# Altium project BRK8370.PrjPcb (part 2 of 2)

## Sheet QSFP-GTH.SchDoc: QSFP-GTH
size C; Author: Casey Smith; Organization: Opal Kelly; Address1: 13500 SW 72nd Ave STE 100; Address2: Portland, OR 97223; Address3: 217.391.3724; Address4: http://www.opalkelly.com; DocumentNumber: 5; Revision: 1; SheetNumber: 5; SheetTotal: 8
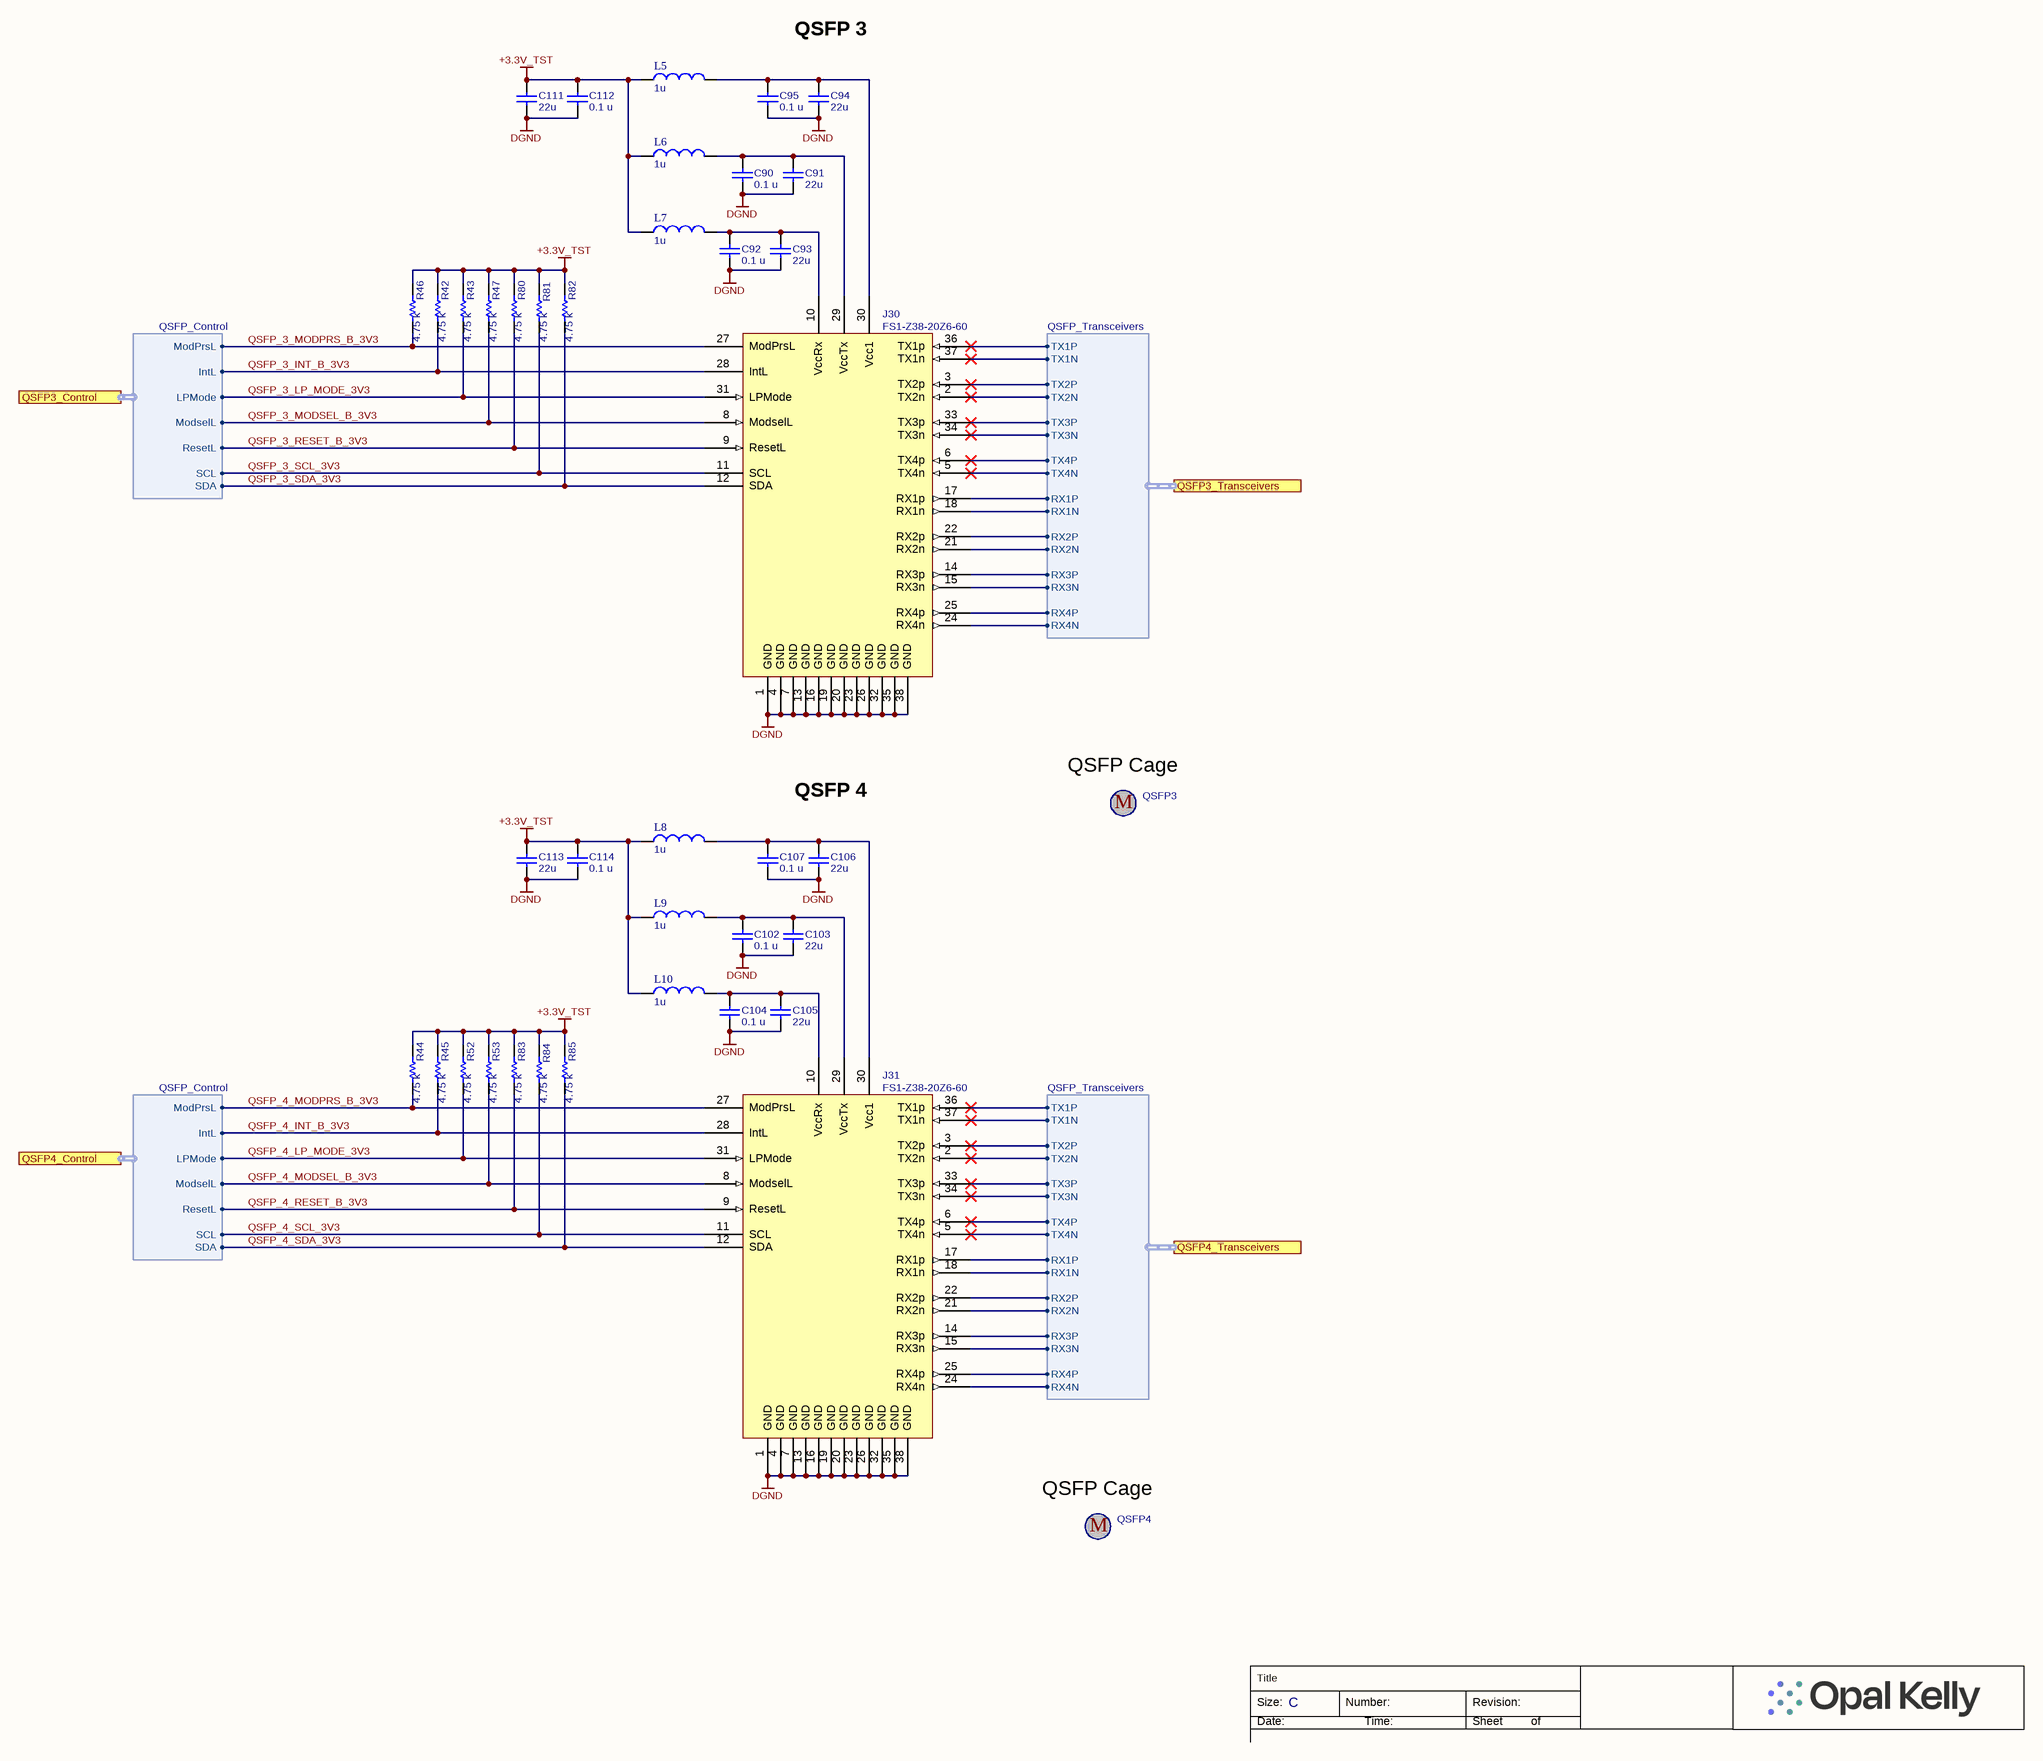
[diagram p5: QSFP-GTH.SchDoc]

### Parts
C90  value 0.1 u  [CAPC1005X06A]  (hidden comment: SM-0402, 10%, 10v)
C91  value 22u  [CAPC3216N]  (hidden comment: SM-1206, 10%, 10v, X7R)
C92  value 0.1 u  [CAPC1005X06A]  (hidden comment: SM-0402, 10%, 10v)
C93  value 22u  [CAPC3216N]  (hidden comment: SM-1206, 10%, 10v, X7R)
C94  value 22u  [CAPC3216N]  (hidden comment: SM-1206, 10%, 10v, X7R)
C95  value 0.1 u  [CAPC1005X06A]  (hidden comment: SM-0402, 10%, 10v)
C102  value 0.1 u  [CAPC1005X06A]  (hidden comment: SM-0402, 10%, 10v)
C103  value 22u  [CAPC3216N]  (hidden comment: SM-1206, 10%, 10v, X7R)
C104  value 0.1 u  [CAPC1005X06A]  (hidden comment: SM-0402, 10%, 10v)
C105  value 22u  [CAPC3216N]  (hidden comment: SM-1206, 10%, 10v, X7R)
C106  value 22u  [CAPC3216N]  (hidden comment: SM-1206, 10%, 10v, X7R)
C107  value 0.1 u  [CAPC1005X06A]  (hidden comment: SM-0402, 10%, 10v)
C111  value 22u  [CAPC3216N]  (hidden comment: SM-1206, 10%, 10v, X7R)
C112  value 0.1 u  [CAPC1005X06A]  (hidden comment: SM-0402, 10%, 10v)
C113  value 22u  [CAPC3216N]  (hidden comment: SM-1206, 10%, 10v, X7R)
C114  value 0.1 u  [CAPC1005X06A]  (hidden comment: SM-0402, 10%, 10v)
J30  FS1-Z38-20Z6-60  [QSFP28_RECEPTACLE_SFF-8679]
J31  FS1-Z38-20Z6-60  [QSFP28_RECEPTACLE_SFF-8679]
L5  value 1u  [CIGT252010]  (hidden comment: CIGT252010LM1R0MNE)
L6  value 1u  [CIGT252010]  (hidden comment: CIGT252010LM1R0MNE)
L7  value 1u  [CIGT252010]  (hidden comment: CIGT252010LM1R0MNE)
L8  value 1u  [CIGT252010]  (hidden comment: CIGT252010LM1R0MNE)
L9  value 1u  [CIGT252010]  (hidden comment: CIGT252010LM1R0MNE)
L10  value 1u  [CIGT252010]  (hidden comment: CIGT252010LM1R0MNE)
QSFP3  Pressfit  [QSFP28_SINGLE_CAGE]  (value not drawn)
QSFP4  Pressfit  [QSFP28_SINGLE_CAGE]  (value not drawn)
R42  value 4.75 k  [RESC1005X06A]  (hidden comment: CRCW04024K75FKED)
R43  value 4.75 k  [RESC1005X06A]  (hidden comment: CRCW04024K75FKED)
R44  value 4.75 k  [RESC1005X06A]  (hidden comment: CRCW04024K75FKED)
R45  value 4.75 k  [RESC1005X06A]  (hidden comment: CRCW04024K75FKED)
R46  value 4.75 k  [RESC1005X06A]  (hidden comment: CRCW04024K75FKED)
R47  value 4.75 k  [RESC1005X06A]  (hidden comment: CRCW04024K75FKED)
R52  value 4.75 k  [RESC1005X06A]  (hidden comment: CRCW04024K75FKED)
R53  value 4.75 k  [RESC1005X06A]  (hidden comment: CRCW04024K75FKED)
R80  value 4.75 k  [RESC1005X06A]  (hidden comment: CRCW04024K75FKED)
R81  value 4.75 k  [RESC1005X06A]  (hidden comment: CRCW04024K75FKED)
R82  value 4.75 k  [RESC1005X06A]  (hidden comment: CRCW04024K75FKED)
R83  value 4.75 k  [RESC1005X06A]  (hidden comment: CRCW04024K75FKED)
R84  value 4.75 k  [RESC1005X06A]  (hidden comment: CRCW04024K75FKED)
R85  value 4.75 k  [RESC1005X06A]  (hidden comment: CRCW04024K75FKED)

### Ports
QSFP3_Control (harness QSFP_Control), QSFP3_Transceivers (harness QSFP_Transceivers), QSFP4_Control (harness QSFP_Control), QSFP4_Transceivers (harness QSFP_Transceivers)

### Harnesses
QSFP_Transceivers: TX1P, TX1N, TX2P, TX2N, TX3P, TX3N, TX4P, TX4N, RX1P, RX1N, RX2P, RX2N, RX3P, RX3N, RX4P, RX4N
QSFP_Control: ModPrsL, IntL, LPMode, ModselL, ResetL, SCL, SDA

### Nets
+3.3V_TST: C111.2 C112.2 C113.2 C114.2 L5.1 L6.1 L7.1 L8.1 L9.1 L10.1 R42.2 R43.2 R44.2 R45.2 R46.2 R47.2 R52.2 R53.2 R80.2 R81.2 R82.2 R83.2 R84.2 R85.2
DGND: C90.1 C91.1 C92.1 C93.1 C94.1 C95.1 C102.1 C103.1 C104.1 C105.1 C106.1 C107.1 C111.1 C112.1 C113.1 C114.1 J30.1(GND) J30.4(GND) J30.7(GND) J30.13(GND) J30.16(GND) J30.19(GND) J30.20(GND) J30.23(GND) J30.26(GND) J30.32(GND) J30.35(GND) J30.38(GND) J31.1(GND) J31.4(GND) J31.7(GND) J31.13(GND) J31.16(GND) J31.19(GND) J31.20(GND) J31.23(GND) J31.26(GND) J31.32(GND) J31.35(GND) J31.38(GND)
QSFP_3_INT_B_3V3: J30.28(IntL) R42.1 ; port QSFP3_Control.IntL
QSFP_3_LP_MODE_3V3: J30.31(LPMode) R43.1 ; port QSFP3_Control.LPMode
QSFP_3_MODPRS_B_3V3: J30.27(ModPrsL) R46.1 ; port QSFP3_Control.ModPrsL
QSFP_3_MODSEL_B_3V3: J30.8(ModselL) R47.1 ; port QSFP3_Control.ModselL
QSFP_3_RESET_B_3V3: J30.9(ResetL) R80.1 ; port QSFP3_Control.ResetL
QSFP_3_RX1_N: J30.18(RX1n) ; port QSFP3_Transceivers.RX1N
QSFP_3_RX1_P: J30.17(RX1p) ; port QSFP3_Transceivers.RX1P
QSFP_3_RX2_N: J30.21(RX2n) ; port QSFP3_Transceivers.RX2N
QSFP_3_RX2_P: J30.22(RX2p) ; port QSFP3_Transceivers.RX2P
QSFP_3_RX3_N: J30.15(RX3n) ; port QSFP3_Transceivers.RX3N
QSFP_3_RX3_P: J30.14(RX3p) ; port QSFP3_Transceivers.RX3P
QSFP_3_RX4_N: J30.24(RX4n) ; port QSFP3_Transceivers.RX4N
QSFP_3_RX4_P: J30.25(RX4p) ; port QSFP3_Transceivers.RX4P
QSFP_3_SCL_3V3: J30.11(SCL) R81.1 ; port QSFP3_Control.SCL
QSFP_3_SDA_3V3: J30.12(SDA) R82.1 ; port QSFP3_Control.SDA
QSFP_3_TX1_N: J30.37(TX1n) ; port QSFP3_Transceivers.TX1N
QSFP_3_TX1_P: J30.36(TX1p) ; port QSFP3_Transceivers.TX1P
QSFP_3_TX2_N: J30.2(TX2n) ; port QSFP3_Transceivers.TX2N
QSFP_3_TX2_P: J30.3(TX2p) ; port QSFP3_Transceivers.TX2P
QSFP_3_TX3_N: J30.34(TX3n) ; port QSFP3_Transceivers.TX3N
QSFP_3_TX3_P: J30.33(TX3p) ; port QSFP3_Transceivers.TX3P
QSFP_3_TX4_N: J30.5(TX4n) ; port QSFP3_Transceivers.TX4N
QSFP_3_TX4_P: J30.6(TX4p) ; port QSFP3_Transceivers.TX4P
QSFP_4_INT_B_3V3: J31.28(IntL) R45.1 ; port QSFP4_Control.IntL
QSFP_4_LP_MODE_3V3: J31.31(LPMode) R52.1 ; port QSFP4_Control.LPMode
QSFP_4_MODPRS_B_3V3: J31.27(ModPrsL) R44.1 ; port QSFP4_Control.ModPrsL
QSFP_4_MODSEL_B_3V3: J31.8(ModselL) R53.1 ; port QSFP4_Control.ModselL
QSFP_4_RESET_B_3V3: J31.9(ResetL) R83.1 ; port QSFP4_Control.ResetL
QSFP_4_RX1_N: J31.18(RX1n) ; port QSFP4_Transceivers.RX1N
QSFP_4_RX1_P: J31.17(RX1p) ; port QSFP4_Transceivers.RX1P
QSFP_4_RX2_N: J31.21(RX2n) ; port QSFP4_Transceivers.RX2N
QSFP_4_RX2_P: J31.22(RX2p) ; port QSFP4_Transceivers.RX2P
QSFP_4_RX3_N: J31.15(RX3n) ; port QSFP4_Transceivers.RX3N
QSFP_4_RX3_P: J31.14(RX3p) ; port QSFP4_Transceivers.RX3P
QSFP_4_RX4_N: J31.24(RX4n) ; port QSFP4_Transceivers.RX4N
QSFP_4_RX4_P: J31.25(RX4p) ; port QSFP4_Transceivers.RX4P
QSFP_4_SCL_3V3: J31.11(SCL) R84.1 ; port QSFP4_Control.SCL
QSFP_4_SDA_3V3: J31.12(SDA) R85.1 ; port QSFP4_Control.SDA
QSFP_4_TX1_N: J31.37(TX1n) ; port QSFP4_Transceivers.TX1N
QSFP_4_TX1_P: J31.36(TX1p) ; port QSFP4_Transceivers.TX1P
QSFP_4_TX2_N: J31.2(TX2n) ; port QSFP4_Transceivers.TX2N
QSFP_4_TX2_P: J31.3(TX2p) ; port QSFP4_Transceivers.TX2P
QSFP_4_TX3_N: J31.34(TX3n) ; port QSFP4_Transceivers.TX3N
QSFP_4_TX3_P: J31.33(TX3p) ; port QSFP4_Transceivers.TX3P
QSFP_4_TX4_N: J31.5(TX4n) ; port QSFP4_Transceivers.TX4N
QSFP_4_TX4_P: J31.6(TX4p) ; port QSFP4_Transceivers.TX4P
NetC90_2: C90.2 C91.2 J30.29(VccTx) L6.2
NetC92_2: C92.2 C93.2 J30.10(VccRx) L7.2
NetC94_2: C94.2 C95.2 J30.30(Vcc1) L5.2
NetC102_2: C102.2 C103.2 J31.29(VccTx) L9.2
NetC104_2: C104.2 C105.2 J31.10(VccRx) L10.2
NetC106_2: C106.2 C107.2 J31.30(Vcc1) L8.2

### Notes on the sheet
- QSFP 3
- (near QSFP3) QSFP Cage
- QSFP 4
- (near QSFP4) QSFP Cage
- Title
- Size:
- Date:
- C
- Number:
- Time:
- Revision:
- Sheet
- of

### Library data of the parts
C90 C92 C95 C102 C104 C107 C112 C114 = 000070: Partnumber: 000070; manufacturer: Kemet; manufacturer_pn: C0402C104K8PACTU; ValueFloat: 1E-7; id: 750; inventory_price: 0.0023; reorder_quantity: 70000; x_tolerance: 10
C91 C93 C94 C103 C105 C106 C111 C113 = 001284: Partnumber: 001284; manufacturer: Taiyo Yuden; manufacturer_pn: LMK316AB7226KL-TR; ValueFloat: 2.2E-5; id: 60625; inventory_price: 0.14; reorder_quantity: 4000; x_tolerance: 10
J30 J31 = 001782: Partnumber: 001782; manufacturer: Amphenol; id: 254667; inventory_price: 4
L5-L10 = 002331: Thin Film, 1uH, 3.1A, 50mOhm, Unshielded; Partnumber: 002331; Manufacturer: Samsung Electro-Mechanics; ValueFloat: 1E-6; Tolerance (%): 20; Description 2: 1008 (2520 Metric)
QSFP3 QSFP4 = 001781: Partnumber: 001781; manufacturer: Amphenol; manufacturer_pn: U95-T111-1001; id: 254666; inventory_price: 3.5
R42-R47 R52 R53 R80-R85 = 001008: Partnumber: 001008; manufacturer: Vishay; ValueFloat: 4750; x_tolerance: 1

## Sheet QSFP-GTY.SchDoc: QSFP-GTY
size C; Author: Casey Smith; Organization: Opal Kelly; Address1: 13500 SW 72nd Ave STE 100; Address2: Portland, OR 97223; Address3: 217.391.3724; Address4: http://www.opalkelly.com; DocumentNumber: 6; Revision: 1; SheetNumber: 6; SheetTotal: 8
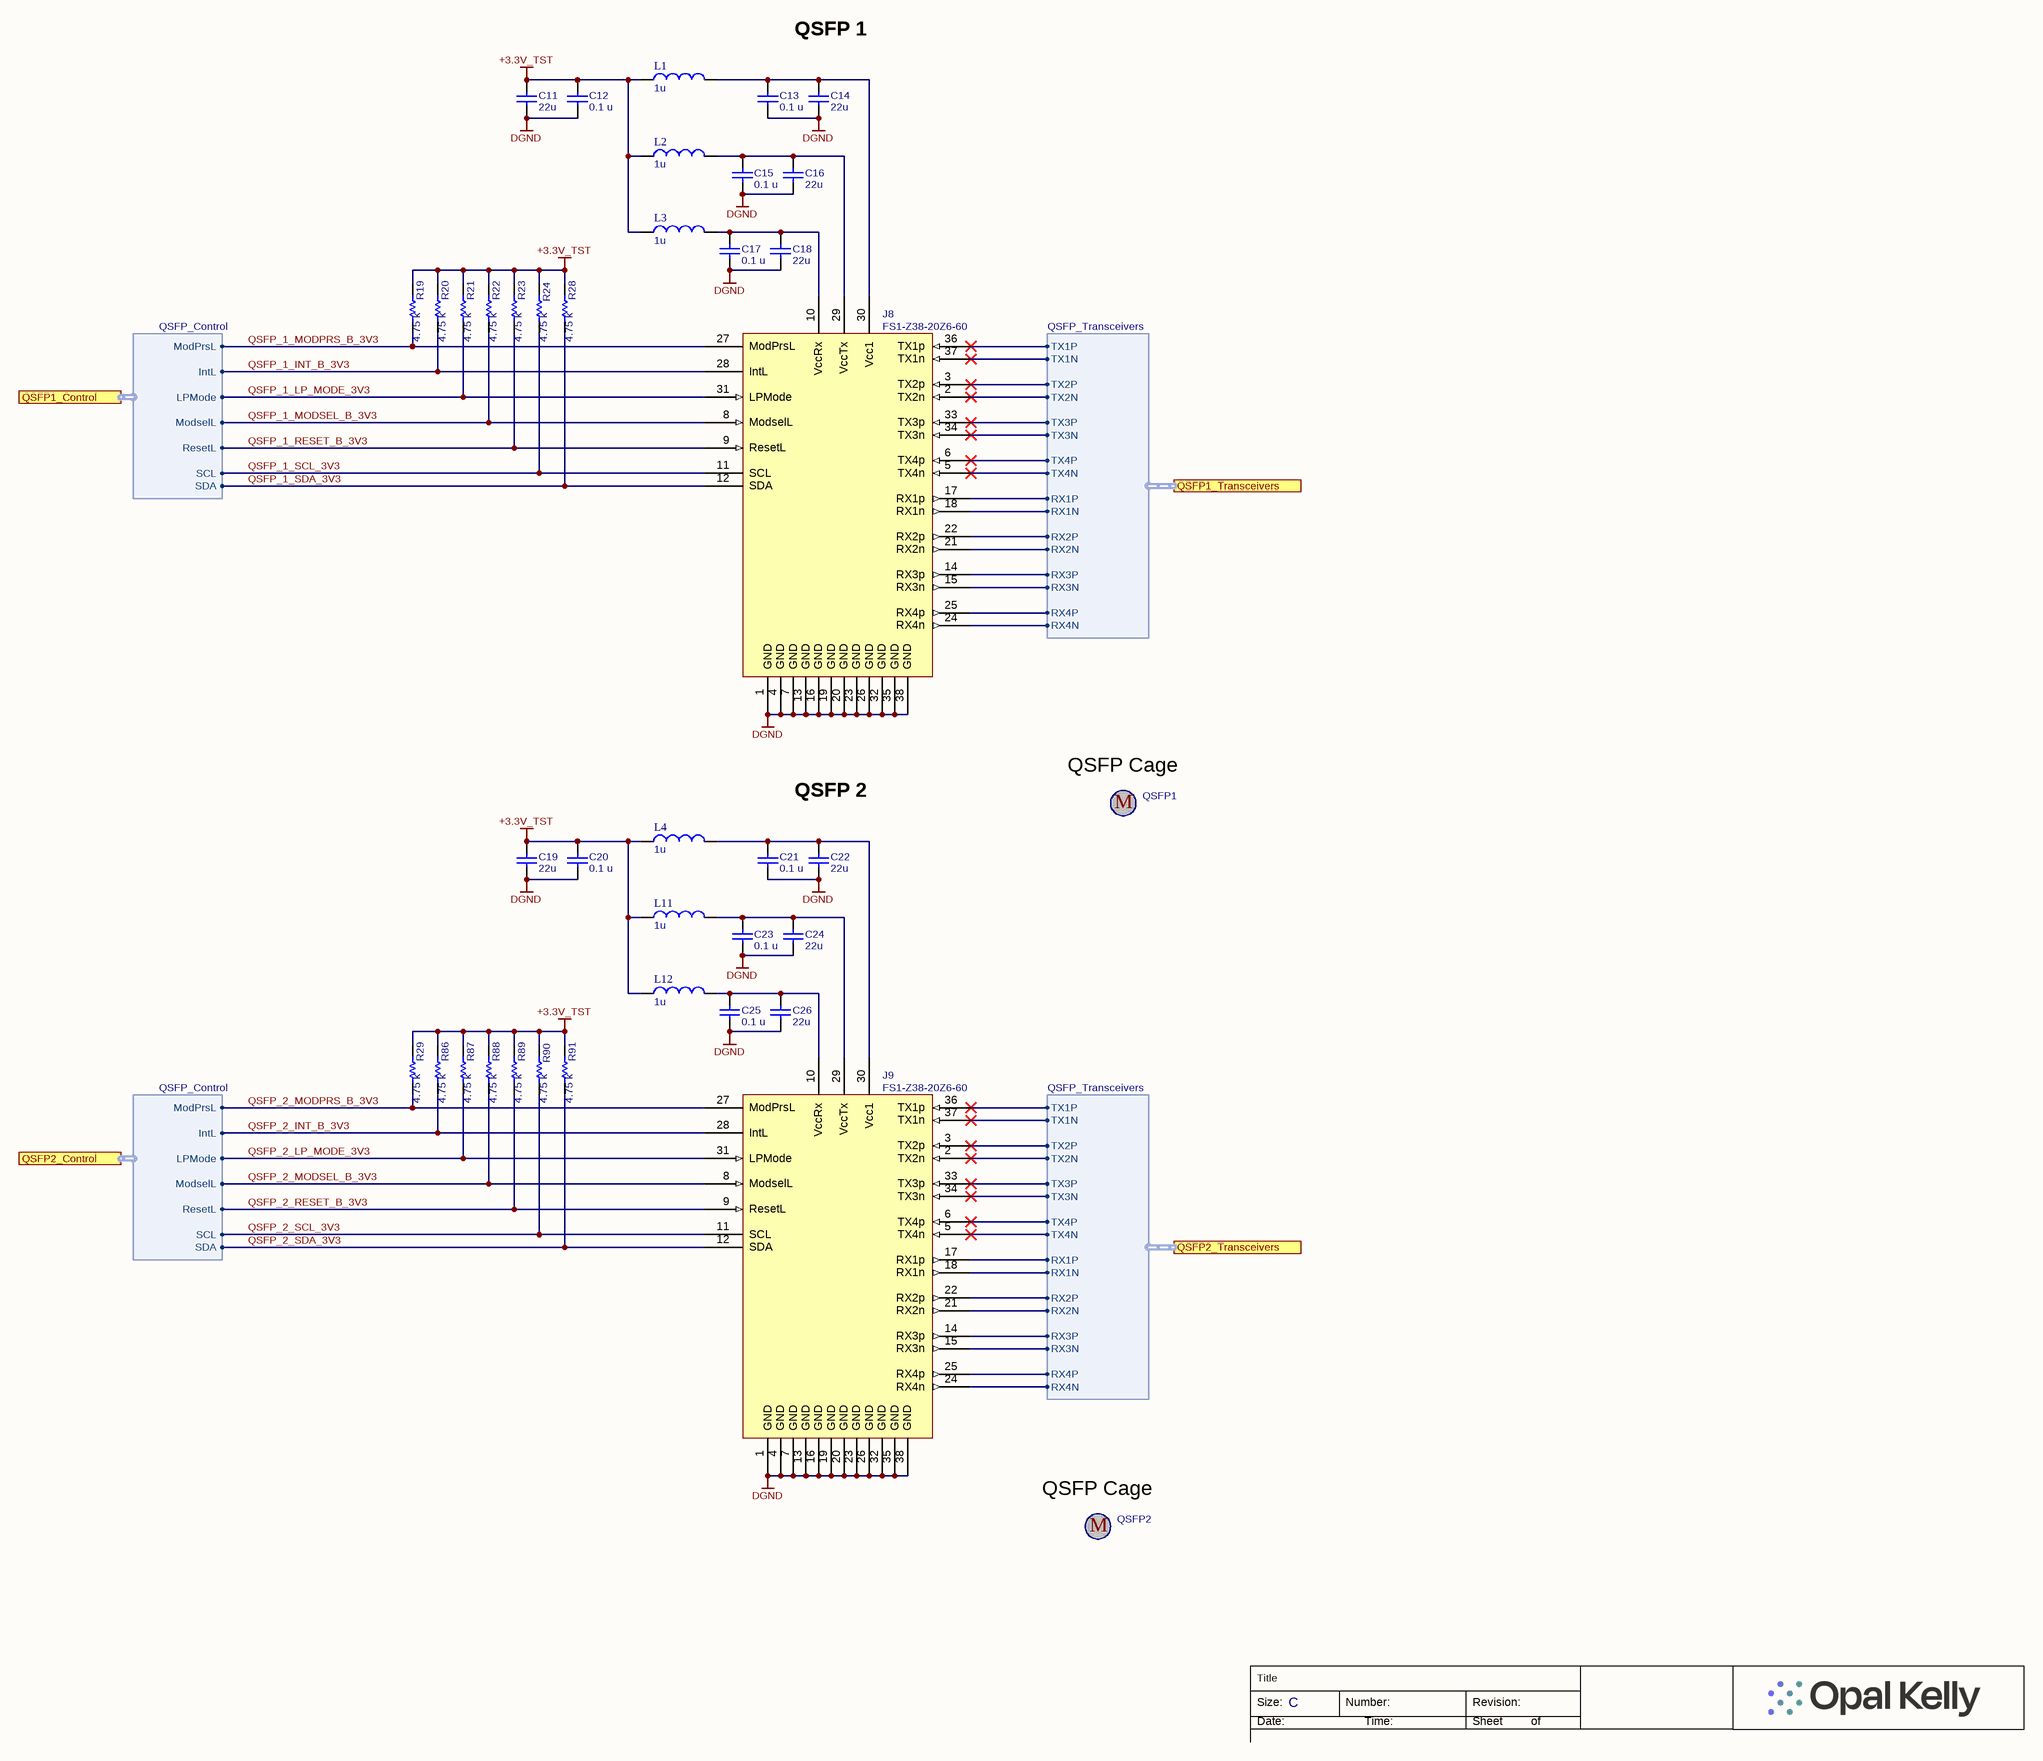
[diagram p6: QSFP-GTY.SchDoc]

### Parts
C11  value 22u  [CAPC3216N]  (hidden comment: SM-1206, 10%, 10v, X7R)
C12  value 0.1 u  [CAPC1005X06A]  (hidden comment: SM-0402, 10%, 10v)
C13  value 0.1 u  [CAPC1005X06A]  (hidden comment: SM-0402, 10%, 10v)
C14  value 22u  [CAPC3216N]  (hidden comment: SM-1206, 10%, 10v, X7R)
C15  value 0.1 u  [CAPC1005X06A]  (hidden comment: SM-0402, 10%, 10v)
C16  value 22u  [CAPC3216N]  (hidden comment: SM-1206, 10%, 10v, X7R)
C17  value 0.1 u  [CAPC1005X06A]  (hidden comment: SM-0402, 10%, 10v)
C18  value 22u  [CAPC3216N]  (hidden comment: SM-1206, 10%, 10v, X7R)
C19  value 22u  [CAPC3216N]  (hidden comment: SM-1206, 10%, 10v, X7R)
C20  value 0.1 u  [CAPC1005X06A]  (hidden comment: SM-0402, 10%, 10v)
C21  value 0.1 u  [CAPC1005X06A]  (hidden comment: SM-0402, 10%, 10v)
C22  value 22u  [CAPC3216N]  (hidden comment: SM-1206, 10%, 10v, X7R)
C23  value 0.1 u  [CAPC1005X06A]  (hidden comment: SM-0402, 10%, 10v)
C24  value 22u  [CAPC3216N]  (hidden comment: SM-1206, 10%, 10v, X7R)
C25  value 0.1 u  [CAPC1005X06A]  (hidden comment: SM-0402, 10%, 10v)
C26  value 22u  [CAPC3216N]  (hidden comment: SM-1206, 10%, 10v, X7R)
J8  FS1-Z38-20Z6-60  [QSFP28_RECEPTACLE_SFF-8679]
J9  FS1-Z38-20Z6-60  [QSFP28_RECEPTACLE_SFF-8679]
L1  value 1u  [CIGT252010]  (hidden comment: CIGT252010LM1R0MNE)
L2  value 1u  [CIGT252010]  (hidden comment: CIGT252010LM1R0MNE)
L3  value 1u  [CIGT252010]  (hidden comment: CIGT252010LM1R0MNE)
L4  value 1u  [CIGT252010]  (hidden comment: CIGT252010LM1R0MNE)
L11  value 1u  [CIGT252010]  (hidden comment: CIGT252010LM1R0MNE)
L12  value 1u  [CIGT252010]  (hidden comment: CIGT252010LM1R0MNE)
QSFP1  Pressfit  [QSFP28_SINGLE_CAGE]  (value not drawn)
QSFP2  Pressfit  [QSFP28_SINGLE_CAGE]  (value not drawn)
R19  value 4.75 k  [RESC1005X06A]  (hidden comment: CRCW04024K75FKED)
R20  value 4.75 k  [RESC1005X06A]  (hidden comment: CRCW04024K75FKED)
R21  value 4.75 k  [RESC1005X06A]  (hidden comment: CRCW04024K75FKED)
R22  value 4.75 k  [RESC1005X06A]  (hidden comment: CRCW04024K75FKED)
R23  value 4.75 k  [RESC1005X06A]  (hidden comment: CRCW04024K75FKED)
R24  value 4.75 k  [RESC1005X06A]  (hidden comment: CRCW04024K75FKED)
R28  value 4.75 k  [RESC1005X06A]  (hidden comment: CRCW04024K75FKED)
R29  value 4.75 k  [RESC1005X06A]  (hidden comment: CRCW04024K75FKED)
R86  value 4.75 k  [RESC1005X06A]  (hidden comment: CRCW04024K75FKED)
R87  value 4.75 k  [RESC1005X06A]  (hidden comment: CRCW04024K75FKED)
R88  value 4.75 k  [RESC1005X06A]  (hidden comment: CRCW04024K75FKED)
R89  value 4.75 k  [RESC1005X06A]  (hidden comment: CRCW04024K75FKED)
R90  value 4.75 k  [RESC1005X06A]  (hidden comment: CRCW04024K75FKED)
R91  value 4.75 k  [RESC1005X06A]  (hidden comment: CRCW04024K75FKED)

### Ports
QSFP1_Control (harness QSFP_Control), QSFP1_Transceivers (harness QSFP_Transceivers), QSFP2_Control (harness QSFP_Control), QSFP2_Transceivers (harness QSFP_Transceivers)

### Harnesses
QSFP_Transceivers: TX1P, TX1N, TX2P, TX2N, TX3P, TX3N, TX4P, TX4N, RX1P, RX1N, RX2P, RX2N, RX3P, RX3N, RX4P, RX4N
QSFP_Control: ModPrsL, IntL, LPMode, ModselL, ResetL, SCL, SDA

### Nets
+3.3V_TST: C11.2 C12.2 C19.2 C20.2 L1.1 L2.1 L3.1 L4.1 L11.1 L12.1 R19.2 R20.2 R21.2 R22.2 R23.2 R24.2 R28.2 R29.2 R86.2 R87.2 R88.2 R89.2 R90.2 R91.2
DGND: C11.1 C12.1 C13.1 C14.1 C15.1 C16.1 C17.1 C18.1 C19.1 C20.1 C21.1 C22.1 C23.1 C24.1 C25.1 C26.1 J8.1(GND) J8.4(GND) J8.7(GND) J8.13(GND) J8.16(GND) J8.19(GND) J8.20(GND) J8.23(GND) J8.26(GND) J8.32(GND) J8.35(GND) J8.38(GND) J9.1(GND) J9.4(GND) J9.7(GND) J9.13(GND) J9.16(GND) J9.19(GND) J9.20(GND) J9.23(GND) J9.26(GND) J9.32(GND) J9.35(GND) J9.38(GND)
QSFP_1_INT_B_3V3: J8.28(IntL) R20.1 ; port QSFP1_Control.IntL
QSFP_1_LP_MODE_3V3: J8.31(LPMode) R21.1 ; port QSFP1_Control.LPMode
QSFP_1_MODPRS_B_3V3: J8.27(ModPrsL) R19.1 ; port QSFP1_Control.ModPrsL
QSFP_1_MODSEL_B_3V3: J8.8(ModselL) R22.1 ; port QSFP1_Control.ModselL
QSFP_1_RESET_B_3V3: J8.9(ResetL) R23.1 ; port QSFP1_Control.ResetL
QSFP_1_RX1_N: J8.18(RX1n) ; port QSFP1_Transceivers.RX1N
QSFP_1_RX1_P: J8.17(RX1p) ; port QSFP1_Transceivers.RX1P
QSFP_1_RX2_N: J8.21(RX2n) ; port QSFP1_Transceivers.RX2N
QSFP_1_RX2_P: J8.22(RX2p) ; port QSFP1_Transceivers.RX2P
QSFP_1_RX3_N: J8.15(RX3n) ; port QSFP1_Transceivers.RX3N
QSFP_1_RX3_P: J8.14(RX3p) ; port QSFP1_Transceivers.RX3P
QSFP_1_RX4_N: J8.24(RX4n) ; port QSFP1_Transceivers.RX4N
QSFP_1_RX4_P: J8.25(RX4p) ; port QSFP1_Transceivers.RX4P
QSFP_1_SCL_3V3: J8.11(SCL) R24.1 ; port QSFP1_Control.SCL
QSFP_1_SDA_3V3: J8.12(SDA) R28.1 ; port QSFP1_Control.SDA
QSFP_1_TX1_N: J8.37(TX1n) ; port QSFP1_Transceivers.TX1N
QSFP_1_TX1_P: J8.36(TX1p) ; port QSFP1_Transceivers.TX1P
QSFP_1_TX2_N: J8.2(TX2n) ; port QSFP1_Transceivers.TX2N
QSFP_1_TX2_P: J8.3(TX2p) ; port QSFP1_Transceivers.TX2P
QSFP_1_TX3_N: J8.34(TX3n) ; port QSFP1_Transceivers.TX3N
QSFP_1_TX3_P: J8.33(TX3p) ; port QSFP1_Transceivers.TX3P
QSFP_1_TX4_N: J8.5(TX4n) ; port QSFP1_Transceivers.TX4N
QSFP_1_TX4_P: J8.6(TX4p) ; port QSFP1_Transceivers.TX4P
QSFP_2_INT_B_3V3: J9.28(IntL) R86.1 ; port QSFP2_Control.IntL
QSFP_2_LP_MODE_3V3: J9.31(LPMode) R87.1 ; port QSFP2_Control.LPMode
QSFP_2_MODPRS_B_3V3: J9.27(ModPrsL) R29.1 ; port QSFP2_Control.ModPrsL
QSFP_2_MODSEL_B_3V3: J9.8(ModselL) R88.1 ; port QSFP2_Control.ModselL
QSFP_2_RESET_B_3V3: J9.9(ResetL) R89.1 ; port QSFP2_Control.ResetL
QSFP_2_RX1_N: J9.18(RX1n) ; port QSFP2_Transceivers.RX1N
QSFP_2_RX1_P: J9.17(RX1p) ; port QSFP2_Transceivers.RX1P
QSFP_2_RX2_N: J9.21(RX2n) ; port QSFP2_Transceivers.RX2N
QSFP_2_RX2_P: J9.22(RX2p) ; port QSFP2_Transceivers.RX2P
QSFP_2_RX3_N: J9.15(RX3n) ; port QSFP2_Transceivers.RX3N
QSFP_2_RX3_P: J9.14(RX3p) ; port QSFP2_Transceivers.RX3P
QSFP_2_RX4_N: J9.24(RX4n) ; port QSFP2_Transceivers.RX4N
QSFP_2_RX4_P: J9.25(RX4p) ; port QSFP2_Transceivers.RX4P
QSFP_2_SCL_3V3: J9.11(SCL) R90.1 ; port QSFP2_Control.SCL
QSFP_2_SDA_3V3: J9.12(SDA) R91.1 ; port QSFP2_Control.SDA
QSFP_2_TX1_N: J9.37(TX1n) ; port QSFP2_Transceivers.TX1N
QSFP_2_TX1_P: J9.36(TX1p) ; port QSFP2_Transceivers.TX1P
QSFP_2_TX2_N: J9.2(TX2n) ; port QSFP2_Transceivers.TX2N
QSFP_2_TX2_P: J9.3(TX2p) ; port QSFP2_Transceivers.TX2P
QSFP_2_TX3_N: J9.34(TX3n) ; port QSFP2_Transceivers.TX3N
QSFP_2_TX3_P: J9.33(TX3p) ; port QSFP2_Transceivers.TX3P
QSFP_2_TX4_N: J9.5(TX4n) ; port QSFP2_Transceivers.TX4N
QSFP_2_TX4_P: J9.6(TX4p) ; port QSFP2_Transceivers.TX4P
NetC13_2: C13.2 C14.2 J8.30(Vcc1) L1.2
NetC15_2: C15.2 C16.2 J8.29(VccTx) L2.2
NetC17_2: C17.2 C18.2 J8.10(VccRx) L3.2
NetC21_2: C21.2 C22.2 J9.30(Vcc1) L4.2
NetC23_2: C23.2 C24.2 J9.29(VccTx) L11.2
NetC25_2: C25.2 C26.2 J9.10(VccRx) L12.2

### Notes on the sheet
- QSFP 1
- (near QSFP1) QSFP Cage
- QSFP 2
- (near QSFP2) QSFP Cage
- Title
- Size:
- Date:
- C
- Number:
- Time:
- Revision:
- Sheet
- of

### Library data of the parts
C11 C14 C16 C18 C19 C22 C24 C26 = 001284: as C91 on sheet QSFP-GTH
C12 C13 C15 C17 C20 C21 C23 C25 = 000070: as C90 on sheet QSFP-GTH
J8 J9 = 001782: as J30 on sheet QSFP-GTH
L1-L4 L11 L12 = 002331: as L5 on sheet QSFP-GTH
QSFP1 QSFP2 = 001781: as QSFP3 on sheet QSFP-GTH
R19-R24 R28 R29 R86-R91 = 001008: as R42-R47 on sheet QSFP-GTH

## Sheet Power.SchDoc: Power
size C; Author: Casey Smith; Organization: Opal Kelly; Address1: 13500 SW 72nd Ave STE 100; Address2: Portland, OR 97223; Address3: 217.391.3724; Address4: http://www.opalkelly.com; DocumentNumber: 7; Revision: 1; SheetNumber: 7; SheetTotal: 8
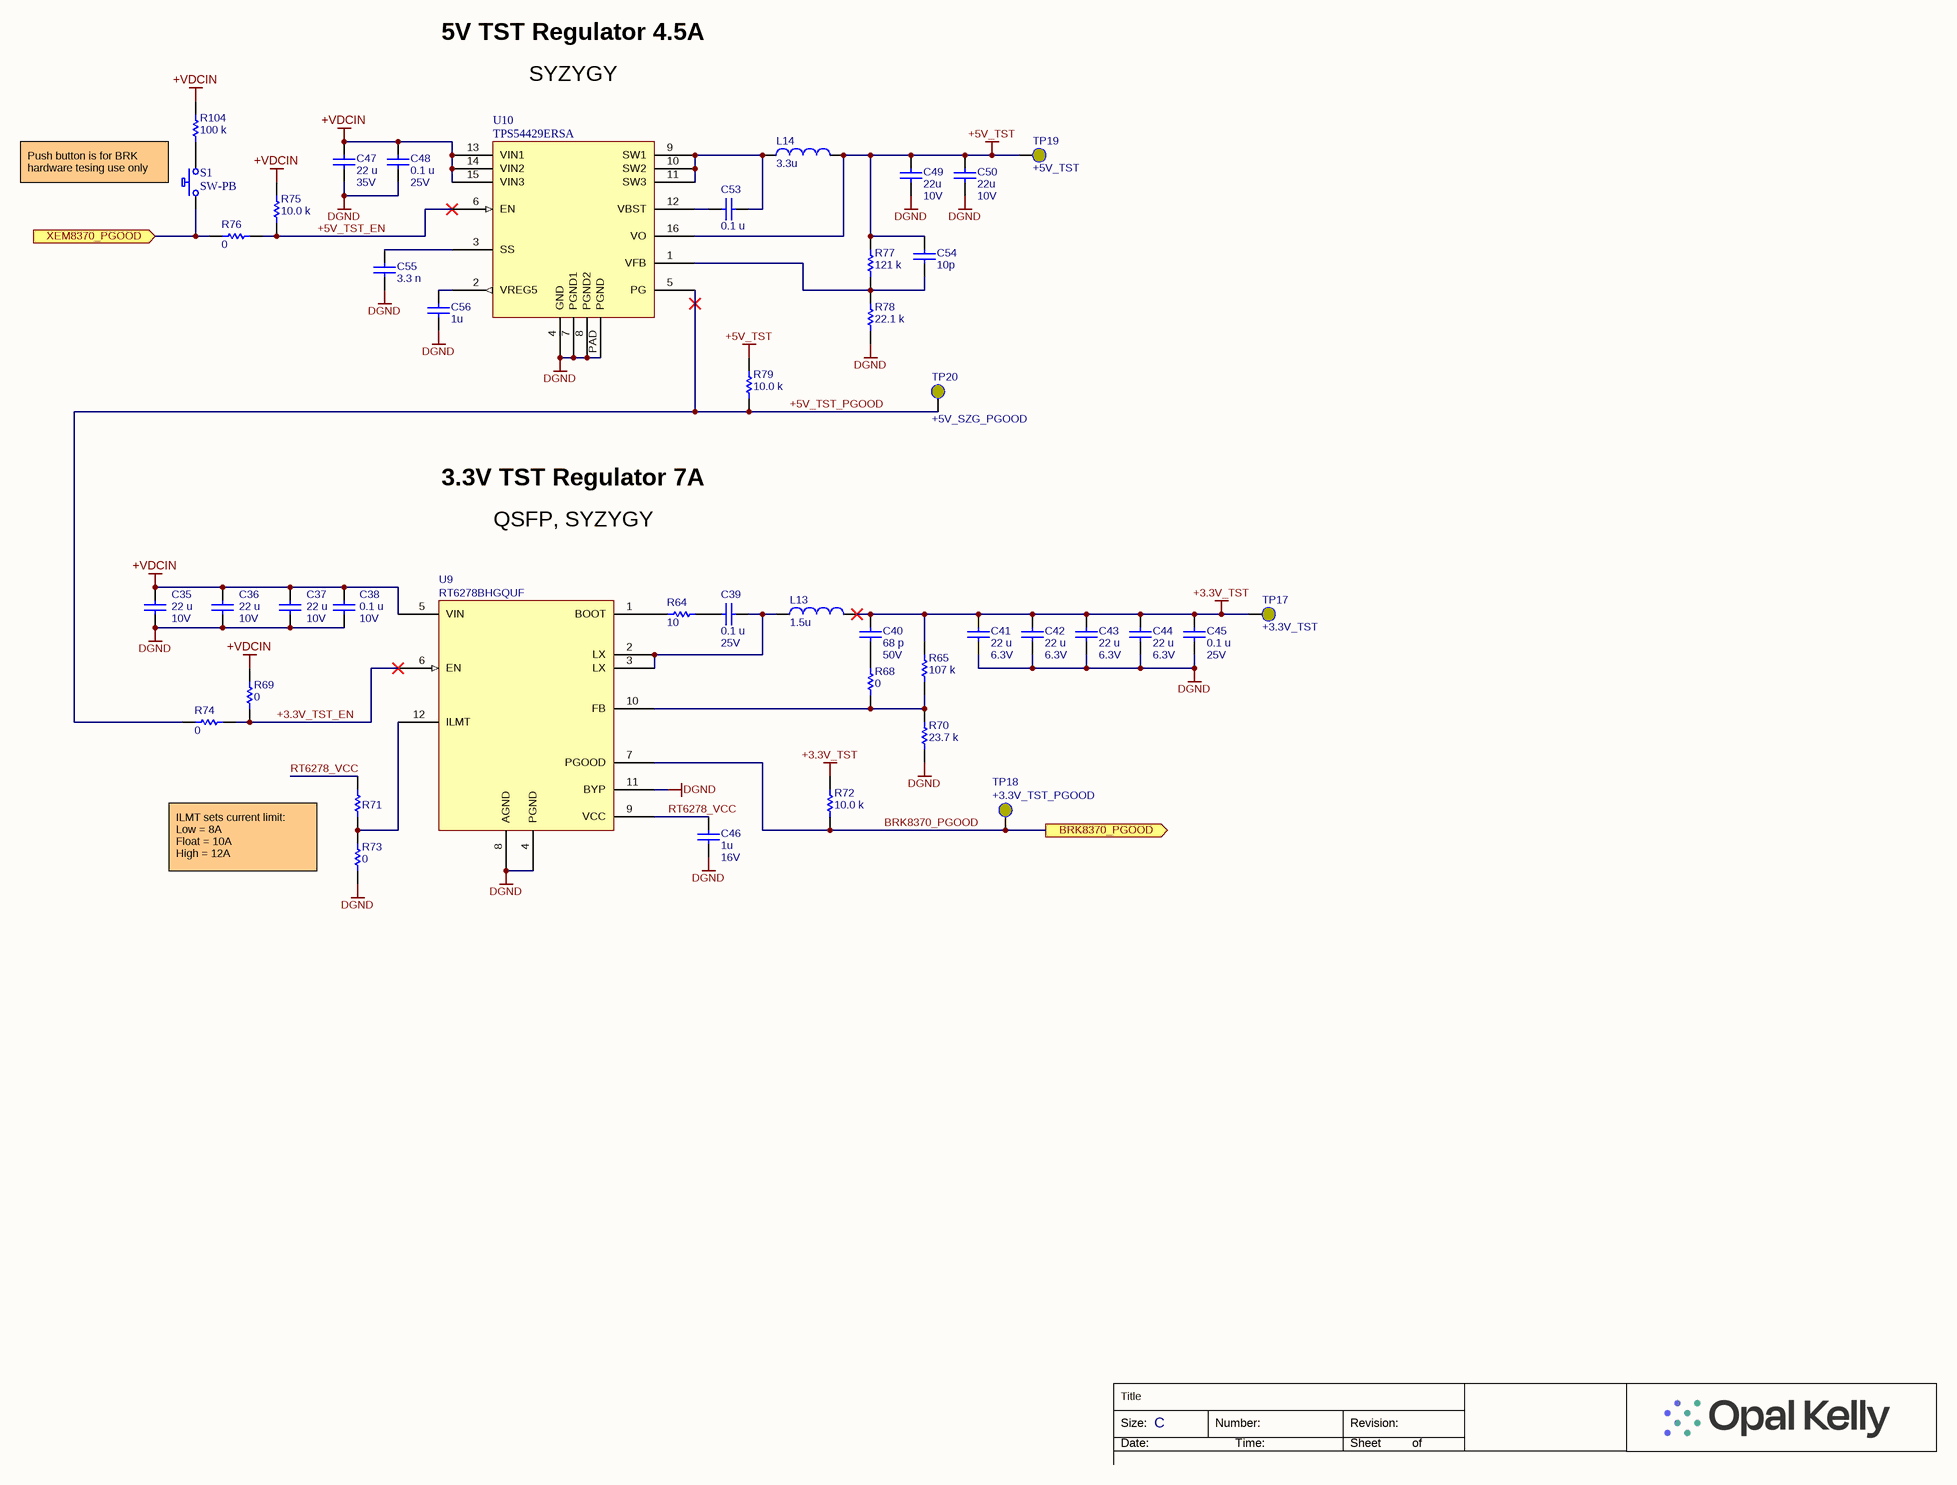
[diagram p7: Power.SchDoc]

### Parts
C35  value 22 u  Voltage: 10V  [CAPC3216N]  (hidden comment: LMK316AB7226KL-TR)
C36  value 22 u  Voltage: 10V  [CAPC3216N]  (hidden comment: LMK316AB7226KL-TR)
C37  value 22 u  Voltage: 10V  [CAPC3216N]  (hidden comment: LMK316AB7226KL-TR)
C38  value 0.1 u  Voltage: 10V  [CAPC1005X06A]  (hidden comment: C0402C104K8PACTU)
C39  value 0.1 u  Voltage: 25V  [CAPC1005X06A]  (hidden comment: TMK105BJ104KV-F)
C40  value 68 p  Voltage: 50V  [CAPC1005X06A]  (hidden comment: C0402C680J5GAC7867)
C41  value 22 u  Voltage: 6.3V  [CAPC2012X14N]  (hidden comment: CL21A226MQQNNNE)
C42  value 22 u  Voltage: 6.3V  [CAPC2012X14N]  (hidden comment: CL21A226MQQNNNE)
C43  value 22 u  Voltage: 6.3V  [CAPC2012X14N]  (hidden comment: CL21A226MQQNNNE)
C44  value 22 u  Voltage: 6.3V  [CAPC2012X14N]  (hidden comment: CL21A226MQQNNNE)
C45  value 0.1 u  Voltage: 25V  [CAPC1005X06A]  (hidden comment: TMK105BJ104KV-F)
C46  value 1u  Voltage: 16V  [CAPC1005X06A]  (hidden comment: EMK105BJ105KV-F)
C47  value 22 u  Voltage: 35V  [CAPC3216N]  (hidden comment: C3216X5R1V226M160AC)
C48  value 0.1 u  Voltage: 25V  [CAPC1005X06A]  (hidden comment: TMK105BJ104KV-F)
C49  value 22u  Voltage: 10V  [CAPC3216N]  (hidden comment: LMK316AB7226KL-TR)
C50  value 22u  Voltage: 10V  [CAPC3216N]  (hidden comment: LMK316AB7226KL-TR)
C53  value 0.1 u  [CAPC1005X06A]  (hidden comment: C0402C104K8PACTU)
C54  value 10p  [CAPC1005X06A]  (hidden comment: CBR04C100J5GAC)
C55  value 3.3 n  [CAPC1005X06A]  (hidden comment: C0402C332K5RACTU)
C56  value 1u  [CAPC1005X06A]  (hidden comment: LMK105BJ105KV-F)
L13  value 1.5u  [0530CDMCCDS]  (hidden comment: 0530CDMCCDS-1R5MC)
L14  value 3.3u  [1267AY]  (hidden comment: 1267AY-3R3N=P3)
R64  value 10  [RESC1005X06A]  (hidden comment: CRCW040210R0FKED)
R65  value 107 k  [RESC1005X06A]  (hidden comment: CRCW0402107KFKED)
R68  value 0  [RESC1005X06A]  (hidden comment: CRCW04020000Z0ED)
R69  value 0  [RESC1005X06A]  (hidden comment: CRCW04020000Z0ED)
R70  value 23.7 k  [RESC1005X06A]  (hidden comment: CRCW040223K7FKED)
R71  Resistor-NoLoad  [RESC1005X06A]  (value not drawn)
R72  value 10.0 k  [RESC1005X06A]  (hidden comment: CRCW040210K0FKED)
R73  value 0  [RESC1005X06A]  (hidden comment: CRCW04020000Z0ED)
R74  value 0  [RESC1005X06A]  (hidden comment: CRCW04020000Z0ED)
R75  value 10.0 k  [RESC1005X06A]  (hidden comment: CRCW040210K0FKED)
R76  value 0  [RESC1005X06A]  (hidden comment: CRCW04020000Z0ED)
R77  value 121 k  [RESC1005X06A]  (hidden comment: CRCW0402121KFKEDC)
R78  value 22.1 k  [RESC1005X06A]  (hidden comment: CRCW040222K1FKEDC)
R79  value 10.0 k  [RESC1005X06A]  (hidden comment: CRCW040210K0FKED)
R104  value 100 k  [RESC1005X06A]  (hidden comment: CRCW0402100KFKED)
S1  SW-PB  [Switch-PCB-wMounts]
TP17  +3.3V_TST  [TP-SMD40]
TP18  +3.3V_TST_PGOOD  [TP-SMD40]
TP19  +5V_TST  [TP-SMD40]
TP20  +5V_SZG_PGOOD  [TP-SMD40]
U9  RT6278BHGQUF  [RT6278]
U10  TPS54429ERSA  [TPS54429E]

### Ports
BRK8370_PGOOD (out), XEM8370_PGOOD (in)

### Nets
+3.3V_TST: C40.2 C41.2 C42.2 C43.2 C44.2 C45.2 L13.2 R65.2 R72.2 TP17.1(PIN)
+5V_TST: C49.2 C50.2 C54.2 L14.2 R77.2 R79.2 TP19.1(PIN) U10.16(VO)
+VDCIN: C35.2 C36.2 C37.2 C38.2 C47.2 C48.2 R69.2 R75.2 R104.2 U9.5(VIN) U10.13(VIN1) U10.14(VIN2) U10.15(VIN3)
DGND: C35.1 C36.1 C37.1 C38.1 C41.1 C42.1 C43.1 C44.1 C45.1 C46.1 C47.1 C48.1 C49.1 C50.1 C55.1 C56.1 R70.1 R73.1 R78.1 U9.4(PGND) U9.8(AGND) U9.11(BYP) U10.4(GND) U10.7(PGND1) U10.8(PGND2) U10.PAD(PGND)
+3.3V_TST_EN: R69.1 R74.1 U9.6(EN)
+5V_TST_EN: R75.1 R76.1 U10.6(EN)
+5V_TST_PGOOD: R74.2 R79.1 TP20.1(PIN) U10.5(PG)
BRK8370_PGOOD: R72.1 TP18.1(PIN) U9.7(PGOOD) ; port BRK8370_PGOOD
RT6278_VCC: C46.2 R71.2 U9.9(VCC)
XEM8370_PGOOD: R76.2 S1.1 ; port XEM8370_PGOOD
NetC39_1: C39.1 R64.2
NetC39_2: C39.2 L13.1 U9.2(LX) U9.3(LX)
NetC40_1: C40.1 R68.2
NetC53_1: C53.1 U10.12(VBST)
NetC53_2: C53.2 L14.1 U10.9(SW1) U10.10(SW2) U10.11(SW3)
NetC54_1: C54.1 R77.1 R78.2 U10.1(VFB)
NetC55_2: C55.2 U10.3(SS)
NetC56_2: C56.2 U10.2(VREG5)
NetR64_1: R64.1 U9.1(BOOT)
NetR65_1: R65.1 R68.1 R70.2 U9.10(FB)
NetR71_1: R71.1 R73.2 U9.12(ILMT)
NetR104_1: R104.1 S1.2

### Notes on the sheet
- 5V TST Regulator 4.5A
- SYZYGY
- Push button is for BRK hardware tesing use only
- 3.3V TST Regulator 7A
- QSFP, SYZYGY
- ILMT sets current limit:
  Low = 8A
  Float = 10A
  High = 12A
- Title
- Size:
- Date:
- C
- Number:
- Time:
- Revision:
- Sheet
- of

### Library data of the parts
C35-C37 = 001284: Ceramic capacitor; Partnumber: 001284; Manufacturer: Taiyo Yuden; ValueFloat: 2.2E-5; Tolerance (%): 10; Description 2: SM-1206, 10%, 10v, X7R
C38 C53 = 000070: Partnumber: 000070; manufacturer: Kemet; ValueFloat: 1E-7; x_tolerance: 10
C39 C45 = 001073: Ceramic capacitor; Partnumber: 001073; Manufacturer: Taiyo Yuden; ValueFloat: 1E-7; Tolerance (%): 10; Description 2: 0402, 25V
C40 = 002342: Partnumber: 002342; manufacturer: Kemet; ValueFloat: 6.8E-11; x_tolerance: 5
C41-C44 = 001792: Partnumber: 001792; manufacturer: Samsung Electro-Mechanics; ValueFloat: 2.2E-5; x_tolerance: 20
C46 = 002255: Partnumber: 002255; manufacturer: Taiyo Yuden; ValueFloat: 1E-6; x_tolerance: 10; x_voltage-rating: 16
C47 = 001172: Partnumber: 001172; manufacturer: TDK; ValueFloat: 2.2E-5; x_tolerance: 20; x_voltage-rating: 35
C48 = 001073: Partnumber: 001073; manufacturer: Taiyo Yuden; ValueFloat: 1E-7; x_tolerance: 10
C49 C50 = 001284: Partnumber: 001284; manufacturer: Taiyo Yuden; ValueFloat: 2.2E-5; x_tolerance: 10
C54 = 001297: Partnumber: 001297; manufacturer: Kemet; ValueFloat: 1E-11; x_tolerance: 5; x_voltage-rating: 50
C55 = 001277: Partnumber: 001277; manufacturer: Kemet; ValueFloat: 3.3E-9; x_tolerance: 10; x_voltage-rating: 50
C56 = 000480: Partnumber: 000480; manufacturer: Taiyo Yuden; ValueFloat: 1E-6; x_tolerance: 10
L13 = 002344: Partnumber: 002344; manufacturer: Sumida; ValueFloat: 1.5E-6; x_tolerance: 20
L14 = 002116: Partnumber: 002116; manufacturer: Murata; ValueFloat: 3.3E-6; x_tolerance: 30
R64 = 000969: Partnumber: 000969; manufacturer: Vishay; x_tolerance: 1
R65 = 000926: Partnumber: 000926; manufacturer: Vishay; ValueFloat: 107000; x_tolerance: 1
R68 R69 R73 R74 R76 = 000755: Partnumber: 000755; manufacturer: Vishay; x_tolerance: 1
R70 = 001119: Partnumber: 001119; manufacturer: Vishay; ValueFloat: 23700; x_tolerance: 1
R71 = 002438: NoLoad resistor; Partnumber: 002438; Manufacturer: Generic
R72 R75 R79 = 001521: Partnumber: 001521; manufacturer: Vishay; ValueFloat: 10000; x_tolerance: 1
R77 = 001872: Partnumber: 001872; manufacturer: Vishay; ValueFloat: 121000; x_tolerance: 1
R78 = 002121: Partnumber: 002121; manufacturer: Vishay; ValueFloat: 22100; x_tolerance: 1
R104 = 001070: Thick-film resistor; Partnumber: 001070; Manufacturer: Vishay; ValueFloat: 100000; Tolerance (%): 1; Description 2: SM-0402, 1%, 1/16W
S1 = SW-PB: Pushbutton; Manufacturer: Generic Components
TP17-TP20 = TESTPOINT-SMD40: Test point, surface-mount, 40mil
U9 = 002341: Partnumber: 002341; manufacturer: Richtek
U10 = 002118: Step-down converter, 4.5 A, 7-18V input, 0.76-5.5V output, 4x4 mm; Partnumber: 002118; Manufacturer: Texas Instruments

## Sheet JTAG.SchDoc: JTAG
size C; Author: Casey Smith; Organization: Opal Kelly; Address1: 13500 SW 72nd Ave STE 100; Address2: Portland, OR 97223; Address3: 217.391.3724; Address4: http://www.opalkelly.com; DocumentNumber: 8; Revision: 1; SheetNumber: 8; SheetTotal: 8
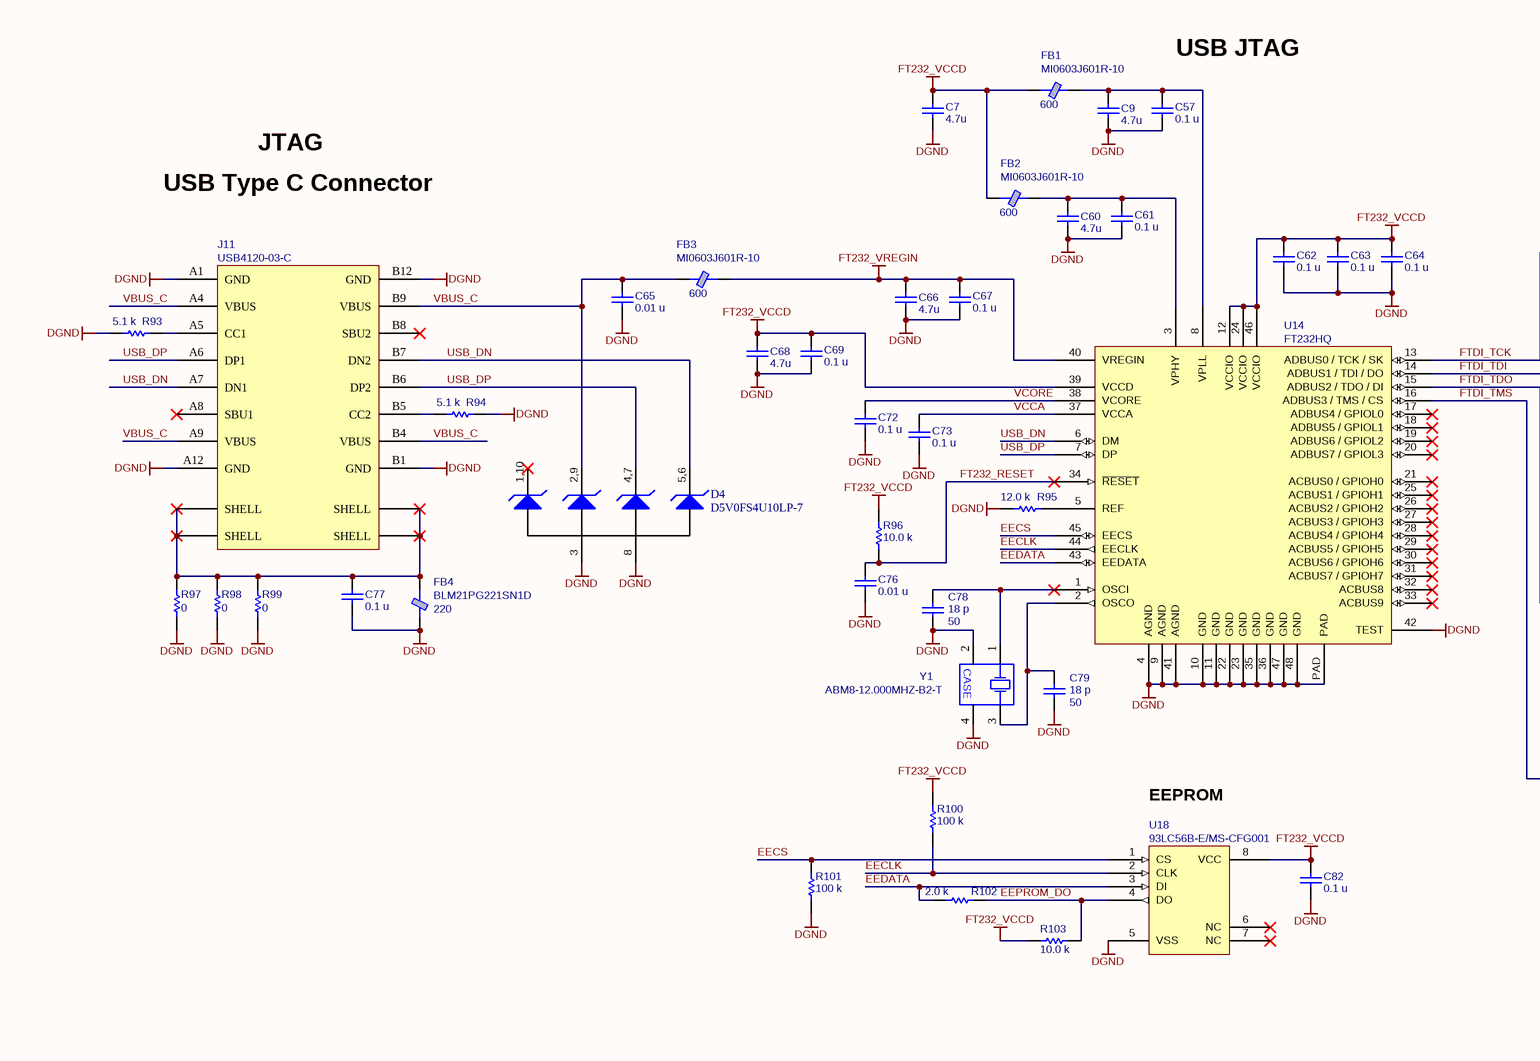
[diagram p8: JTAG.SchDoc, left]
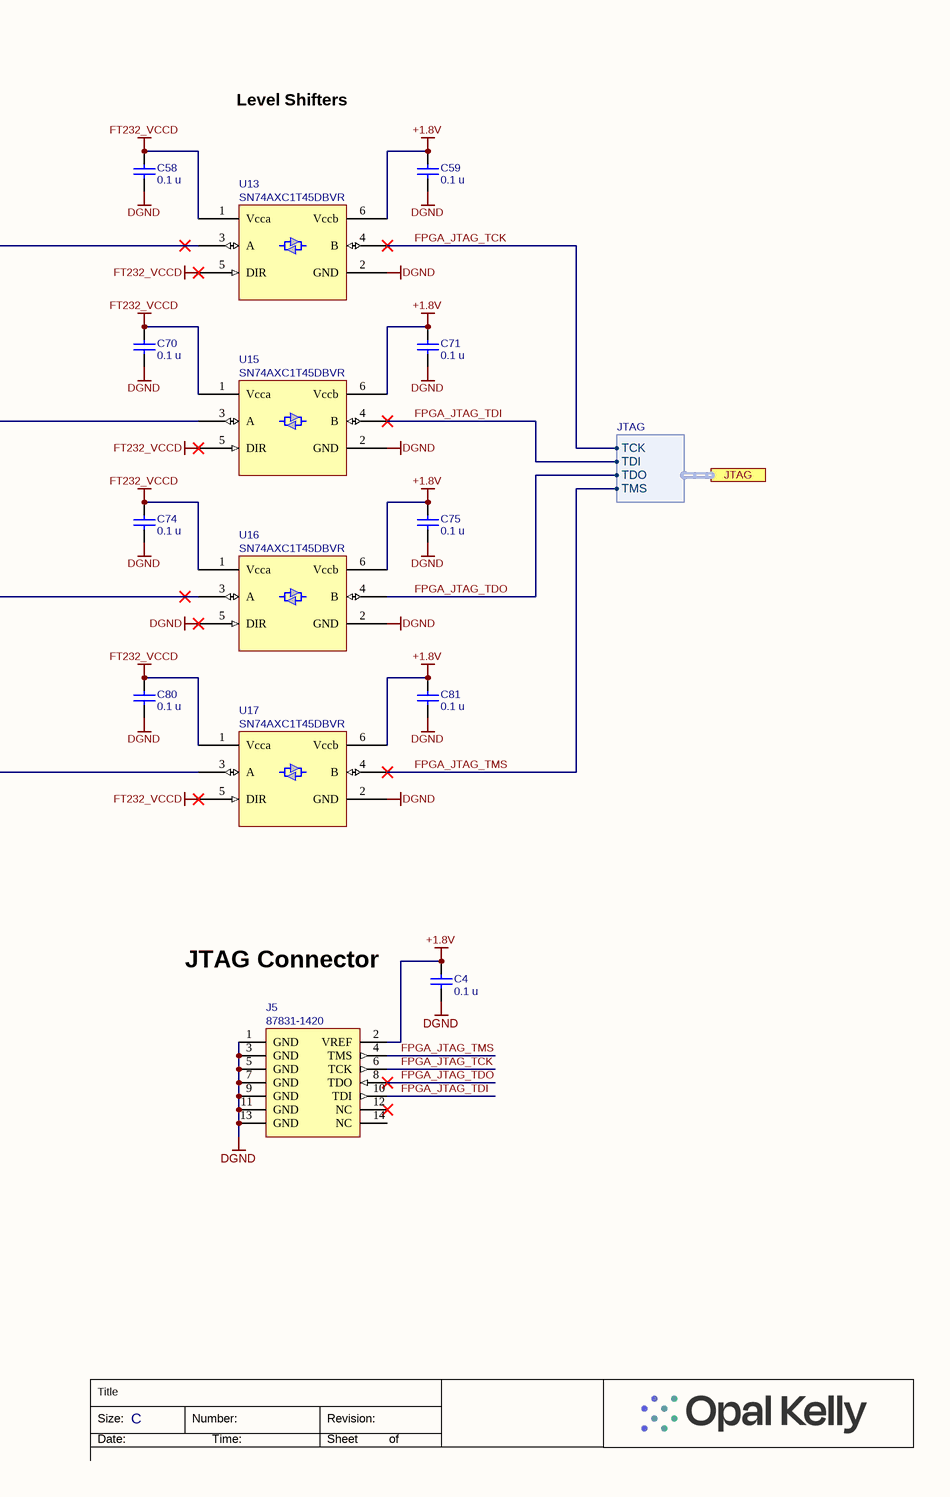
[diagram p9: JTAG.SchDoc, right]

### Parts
C4  value 0.1 u  [CAPC1005X06A]  (hidden comment: SM-0402, 10%, 10v)
C7  value 4.7u  [CAPC1005X06A]  (hidden comment: JMK105BBJ475MV-F)
C9  value 4.7u  [CAPC1005X06A]  (hidden comment: JMK105BBJ475MV-F)
C57  value 0.1 u  [CAPC1005X06A]  (hidden comment: C0402C104K8PACTU)
C58  value 0.1 u  [CAPC1005X06A]  (hidden comment: C0402C104K8PACTU)
C59  value 0.1 u  [CAPC1005X06A]  (hidden comment: C0402C104K8PACTU)
C60  value 4.7u  [CAPC1005X06A]  (hidden comment: JMK105BBJ475MV-F)
C61  value 0.1 u  [CAPC1005X06A]  (hidden comment: C0402C104K8PACTU)
C62  value 0.1 u  [CAPC1005X06A]  (hidden comment: C0402C104K8PACTU)
C63  value 0.1 u  [CAPC1005X06A]  (hidden comment: C0402C104K8PACTU)
C64  value 0.1 u  [CAPC1005X06A]  (hidden comment: C0402C104K8PACTU)
C65  value 0.01 u  [CAPC1005X06A]  (hidden comment: C0402C103K4RACTU)
C66  value 4.7u  [CAPC1005X06A]  (hidden comment: JMK105BBJ475MV-F)
C67  value 0.1 u  [CAPC1005X06A]  (hidden comment: C0402C104K8PACTU)
C68  value 4.7u  [CAPC1005X06A]  (hidden comment: JMK105BBJ475MV-F)
C69  value 0.1 u  [CAPC1005X06A]  (hidden comment: C0402C104K8PACTU)
C70  value 0.1 u  [CAPC1005X06A]  (hidden comment: C0402C104K8PACTU)
C71  value 0.1 u  [CAPC1005X06A]  (hidden comment: C0402C104K8PACTU)
C72  value 0.1 u  [CAPC1005X06A]  (hidden comment: C0402C104K8PACTU)
C73  value 0.1 u  [CAPC1005X06A]  (hidden comment: C0402C104K8PACTU)
C74  value 0.1 u  [CAPC1005X06A]  (hidden comment: C0402C104K8PACTU)
C75  value 0.1 u  [CAPC1005X06A]  (hidden comment: C0402C104K8PACTU)
C76  value 0.01 u  [CAPC1005X06A]  (hidden comment: C0402C103K4RACTU)
C77  value 0.1 u  [CAPC1005X06A]  (hidden comment: SM-0402, 10%, 10v)
C78  value 18 p  Voltage: 50  [CAPC1005X06A]  (hidden comment: C0402C180J5GACTU)
C79  value 18 p  Voltage: 50  [CAPC1005X06A]  (hidden comment: C0402C180J5GACTU)
C80  value 0.1 u  [CAPC1005X06A]  (hidden comment: C0402C104K8PACTU)
C81  value 0.1 u  [CAPC1005X06A]  (hidden comment: C0402C104K8PACTU)
C82  value 0.1 u  [CAPC1005X06A]  (hidden comment: C0402C104K8PACTU)
D4  D5V0FS4U10LP-7  [D5V0FS4U10LP]
FB1  MI0603J601R-10  value 600  [INDC1608X06N]
FB2  MI0603J601R-10  value 600  [INDC1608X06N]
FB3  MI0603J601R-10  value 600  [INDC1608X06N]
FB4  BLM21PG221SN1D  value 220  [RESC2012N]
J5  87831-1420  [XILINX-JTAG]
J11  USB4120-03-C  [USB4120-03-C]
R93  value 5.1 k  [RESC1005X06A]  (hidden comment: CRCW04025K10FKEDC)
R94  value 5.1 k  [RESC1005X06A]  (hidden comment: CRCW04025K10FKEDC)
R95  value 12.0 k  [RESC1005X06A]  (hidden comment: CRCW040212K0FKED)
R96  value 10.0 k  [RESC1005X06A]  (hidden comment: CRCW040210K0FKED)
R97  value 0  [RESC1005X06A]  (hidden comment: CRCW04020000Z0ED)
R98  value 0  [RESC1005X06A]  (hidden comment: CRCW04020000Z0ED)
R99  value 0  [RESC1005X06A]  (hidden comment: CRCW04020000Z0ED)
R100  value 100 k  [RESC1005X06A]  (hidden comment: CRCW0402100KFKED)
R101  value 100 k  [RESC1005X06A]  (hidden comment: CRCW0402100KFKED)
R102  value 2.0 k  [RESC1005X06A]  (hidden comment: CRCW04022K00FKED)
R103  value 10.0 k  [RESC1005X06A]  (hidden comment: CRCW040210K0FKED)
U13  SN74AXC1T45DBVR  [SOT23-6]
U14  FT232HQ  [FT232HQ]
U15  SN74AXC1T45DBVR  [SOT23-6]
U16  SN74AXC1T45DBVR  [SOT23-6]
U17  SN74AXC1T45DBVR  [SOT23-6]
U18  93LC56B-E/MS-CFG001  [MSOP-MS8_N]
Y1  ABM8-12.000MHZ-B2-T  [ABM8]

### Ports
JTAG (harness JTAG)

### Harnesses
JTAG: TDI, TDO, TCK, TMS

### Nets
+1.8V: C4.2 C59.2 C71.2 C75.2 C81.2 J5.2(VREF) U13.6(Vccb) U15.6(Vccb) U16.6(Vccb) U17.6(Vccb)
DGND: C4.1 C7.1 C9.1 C57.1 C58.1 C59.1 C60.1 C61.1 C62.1 C63.1 C64.1 C65.1 C66.1 C67.1 C68.1 C69.1 C70.1 C71.1 C72.1 C73.1 C74.1 C75.1 C76.1 C77.1 C78.1 C79.1 C80.1 C81.1 C82.1 D4.3(A) D4.8(A) FB4.2 J5.1(GND) J5.3(GND) J5.5(GND) J5.7(GND) J5.9(GND) J5.11(GND) J5.13(GND) J11.A1(GND) J11.A12(GND) J11.B1(GND) J11.B12(GND) R93.1 R94.2 R95.1 R97.2 R98.2 R99.2 R101.1 U13.2(GND) U14.4(AGND) U14.9(AGND) U14.10(GND) U14.11(GND) U14.22(GND) U14.23(GND) U14.35(GND) U14.36(GND) U14.41(AGND) U14.42(TEST) U14.47(GND) U14.48(GND) U14.PAD U15.2(GND) U16.2(GND) U16.5(DIR) U17.2(GND) U18.5(VSS) Y1.2(CASE) Y1.4(CASE)
FT232_VCCD: C7.2 C58.2 C62.2 C63.2 C64.2 C68.2 C69.2 C70.2 C74.2 C80.2 C82.2 FB1.1 FB2.1 R96.2 R100.2 R103.2 U13.1(Vcca) U13.5(DIR) U14.12(VCCIO) U14.24(VCCIO) U14.39(VCCD) U14.46(VCCIO) U15.1(Vcca) U15.5(DIR) U16.1(Vcca) U17.1(Vcca) U17.5(DIR) U18.8(VCC)
FT232_VREGIN: C66.2 C67.2 FB3.1 U14.40(VREGIN)
EECLK: R100.1 U14.44(EECLK) U18.2(CLK)
EECS: R101.2 U14.45(EECS) U18.1(CS)
EEDATA: R102.1 U14.43(EEDATA) U18.3(DI)
EEPROM_DO: R102.2 R103.1 U18.4(DO)
FPGA_JTAG_TCK: J5.6(TCK) U13.4(B) ; port JTAG.TCK
FPGA_JTAG_TDI: J5.10(TDI) U15.4(B) ; port JTAG.TDI
FPGA_JTAG_TDO: J5.8(TDO) U16.4(B) ; port JTAG.TDO
FPGA_JTAG_TMS: J5.4(TMS) U17.4(B) ; port JTAG.TMS
FT232_RESET: C76.2 R96.1 U14.34(~{RESET})
FTDI_TCK: U13.3(A) U14.13(ADBUS0_/_TCK_/_SK)
FTDI_TDI: U14.14(ADBUS1_/_TDI_/_DO) U15.3(A)
FTDI_TDO: U14.15(ADBUS2_/_TDO_/_DI) U16.3(A)
FTDI_TMS: U14.16(ADBUS3_/_TMS_/_CS) U17.3(A)
USB_DN: D4.5,6(K) J11.A7(DN1) J11.B7(DN2) U14.6(DM)
USB_DP: D4.4,7(K) J11.A6(DP1) J11.B6(DP2) U14.7(DP)
VBUS_C: C65.2 D4.2,9(K) FB3.2 J11.A4(VBUS) J11.A9(VBUS) J11.B4(VBUS) J11.B9(VBUS)
VCCA: C73.2 U14.37(VCCA)
VCORE: C72.2 U14.38(VCORE)
NetC9_2: C9.2 C57.2 FB1.2 U14.8(VPLL)
NetC60_2: C60.2 C61.2 FB2.2 U14.3(VPHY)
NetC77_2: C77.2 FB4.1 J11.M1(SHELL) J11.M2(SHELL) J11.M3(SHELL) J11.M4(SHELL) R97.1 R98.1 R99.1
NetC78_2: C78.2 U14.1(OSCI) Y1.1(OSC1)
NetC79_2: C79.2 U14.2(OSCO) Y1.3(OSC2)
NetJ11_A5: J11.A5(CC1) R93.2
NetJ11_B5: J11.B5(CC2) R94.1
NetR95_2: R95.2 U14.5(REF)

Not connected (* = marked no-connect by the designer): D4 1,10(K)*; J5 12(NC)* 14(NC); J11 A8(SBU1)* B8(SBU2)*; U14 17(ADBUS4_/_GPIOL0)* 18(ADBUS5_/_GPIOL1)* 19(ADBUS6_/_GPIOL2)* 20(ADBUS7_/_GPIOL3)* 21(ACBUS0_/_GPIOH0)* 25(ACBUS1_/_GPIOH1)* 26(ACBUS2_/_GPIOH2)* 27(ACBUS3_/_GPIOH3)* 28(ACBUS4_/_GPIOH4)* 29(ACBUS5_/_GPIOH5)* 30(ACBUS6_/_GPIOH6)* 31(ACBUS7_/_GPIOH7)* 32(ACBUS8)* 33(ACBUS9)*; U18 6(NC)* 7(NC)*

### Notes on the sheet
- (near C57) USB JTAG
- Level Shifters
- JTAG
- USB Type C Connector
- EEPROM
- JTAG Connector
- Title
- Size:
- Date:
- C
- Number:
- Time:
- Revision:
- Sheet
- of

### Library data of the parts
C4 C77 = 000070: as C90 on sheet QSFP-GTH
C7 = 000824: Partnumber: 000824; manufacturer: Taiyo Yuden; ValueFloat: 4.7E-6; x_tolerance: 20
C9 C60 C66 C68 = 000824: Ceramic capacitor; Manufacturer: Taiyo Yuden; partnumber: 000824; Description 2: 0402, 6.3V; ValueFloat: 4.7E-6; Tolerance (%): 20; x_lifecycle_status: Production
C57-C59 C61-C64 C67 C69-C75 C80-C82 = 000070: as C38 on sheet Power
C65 C76 = 000295: Ceramic Capacitor; Partnumber: 000295; Manufacturer: Kemet; ValueFloat: 1E-8; Tolerance (%): 10; Description 2: SM-0402, 10%, 16V, X5R
C78 C79 = 001640: Ceramic capacitor; Partnumber: 001640; Manufacturer: Kemet; ValueFloat: 1.8E-11; Tolerance (%): 5; Description 2: SM-0402, 5%, 50v, C0G
D4 = 002405: 4 channel TVS diode array; Manufacturer: Diodes Incorporated; PartNumber: 002405; Class I: Discrete; Class II: Diode - Zener; Description 2: USB, TVS
FB1-FB3 = 000569: Ferrite bead; Partnumber: 000569; Manufacturer: Steward; Description 2: SM-0603, 1 A, 600 ohm at 100 MHz
FB4 = 000783: Ferrite Chip; Manufacturer: Murata; partnumber: 000783; Description 2: 220 OHM 2000MA 0805
J5 = 000541: 2mm header, shrouded; Manufacturer: Molex; partnumber: 000541; Description 2: Dual-row, 14-pos, Xilinx JTAG compatible
J11 = 002404: USB 2.0 Type-C receptacle vertical-mount; Partnumber: 002404; Manufacturer: GCT; Description 2: Surface-mount, Vertical-mount
R93 R94 = 001919: Thick-film resistor; Partnumber: 001919; Manufacturer: Vishay; ValueFloat: 5100; Tolerance (%): 1; Description 2: SM-0402, 1%, 1/16W
R95 = 000826: Thick-film resistor; Partnumber: 000826; Manufacturer: Vishay; ValueFloat: 12000; Tolerance (%): 1; Description 2: SM-0402, 1%, 1/16W
R96 R103 = 001521: Thick-film resistor; Partnumber: 001521; Manufacturer: Vishay; ValueFloat: 10000; Tolerance (%): 1; Description 2: SM-0402, 1%, 1/16W
R97-R99 = 000755: Thick-film resistor; Manufacturer: Vishay; partnumber: 000755; Description 2: SM-0402, 1%, 1/16W; Tolerance (%): 1
R100 R101 = 001070: as R104 on sheet Power
R102 = 001162: Thick-film resistor; Partnumber: 001162; Manufacturer: Vishay; ValueFloat: 2000; Tolerance (%): 1; Description 2: SM-0402, 1%, 1/16W
U13 U15-U17 = 002400: Level Translator, 0.65V - 3.6V, Direction Control; Partnumber: 002400; Manufacturer: Texas Instruments; Description 2: Single Bit, Dual Supplies, SOT23-6
U14 = 002398: Partnumber: 002398; manufacturer: FTDI
U18 = 002441: Partnumber: 002441; manufacturer: Opal Kelly Incorporated
Y1 = 002402: Crystal; Partnumber: 002402; Manufacturer: Abracon; Description 2: 12.0 MHz, +/- 50ppm, 3.2mm x 2.5mm, 18 pF

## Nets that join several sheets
+1.8V: Top (TP3.1), MC1 (C34.2 U4.1 U4.6), MC2 (18 pins), JTAG (10 pins)
+3.3V_TST: MC1 (9 pins), MC2 (7 pins), MC3 (J4.40 J6.40 J7.40), QSFP-GTH (24 pins), QSFP-GTY (24 pins), Power (10 pins)
+5V_TST: MC1 (J3.2), MC2 (J14.2), MC3 (J4.2 J6.2 J7.2), Power (8 pins)
+VDCIN: Top (10 pins), MC2 (10 pins), Power (13 pins)
DGND: Top (13 pins), MC1 (61 pins), MC2 (24 pins), MC3 (53 pins), QSFP-GTH (40 pins), QSFP-GTY (40 pins), Power (26 pins), JTAG (71 pins)
GNDADC: Top (TP4.1), MC2 (MC2.28)
VBATT: Top (TP8.1), MC2 (MC2.13)
VCCADC: Top (TP2.1), MC2 (MC2.26)
VCCO_64_66: Top (TP7.1), MC2 (J14.39), MC3 (J6.39 J7.39 MC3.35 MC5.39)
VCCO_67_68_69: Top (TP5.1), MC1 (39 pins), MC3 (J4.39 MC3.31 MC5.40)
VCCO_88_89: Top (TP9.1), MC3 (MC3.130 MC6.49)
VREFP: Top (TP6.1), MC2 (MC2.27)
B68_L14N: MC1 (MC1.91), MC3 (MC5.19)
B68_L14P: MC1 (MC1.89), MC3 (MC5.17)
B68_L16N: MC1 (MC1.75), MC3 (MC5.3)
B68_L16P: MC1 (MC1.73), MC3 (MC5.1)
B68_L19N: MC1 (MC1.79), MC3 (MC5.7)
B68_L19P: MC1 (MC1.77), MC3 (MC5.5)
B68_L20N: MC1 (MC1.83), MC3 (MC5.11)
B68_L20P: MC1 (MC1.81), MC3 (MC5.9)
B68_L23N: MC1 (MC1.87), MC3 (MC5.15)
B68_L23P: MC1 (MC1.85), MC3 (MC5.13)
B69_L3P: MC1 (MC1.142), MC3 (MC5.22)
B69_L5N: MC1 (MC1.136), MC3 (MC5.16)
B69_L5P: MC1 (MC1.134), MC3 (MC5.14)
B69_L11N: MC1 (MC1.128), MC3 (MC5.8)
B69_L11P: MC1 (MC1.126), MC3 (MC5.6)
B69_L20N: MC1 (MC1.140), MC3 (MC5.20)
B69_L20P: MC1 (MC1.138), MC3 (MC5.18)
B69_L21N: MC1 (MC1.124), MC3 (MC5.4)
B69_L21P: MC1 (MC1.122), MC3 (MC5.2)
B69_L24N: MC1 (MC1.132), MC3 (MC5.12)
B69_L24P: MC1 (MC1.130), MC3 (MC5.10)
BRK8370_PGOOD: Top (Q2.5 TP22.1), Power (R72.1 TP18.1 U9.7)
FPGA_JTAG_TCK: MC2 (MC2.22), JTAG (J5.6 U13.4)
FPGA_JTAG_TDI: MC2 (MC2.18), JTAG (J5.10 U15.4)
FPGA_JTAG_TDO: MC2 (MC2.20), JTAG (J5.8 U16.4)
FPGA_JTAG_TMS: MC2 (MC2.24), JTAG (J5.4 U17.4)
PORTB_S16: MC1 (MC1.178), MC3 (J4.21)
PORTB_S18: MC1 (MC1.176), MC3 (J4.23)
PORTB_S20: MC1 (MC1.180), MC3 (J4.25)
PORTE_C2P_CLK_N: MC2 (J14.36), MC3 (MC3.180)
PORTE_C2P_CLK_P: MC2 (J14.34), MC3 (MC3.178)
PORTE_P2C_CLK_N: MC2 (J14.35), MC3 (MC3.156)
PORTE_P2C_CLK_P: MC2 (J14.33), MC3 (MC3.154)
PORTE_S0: MC2 (J14.14), MC3 (MC3.158)
PORTE_S1: MC2 (J14.16), MC3 (MC3.166)
PORTE_S2: MC2 (J14.17), MC3 (MC3.164)
PORTE_S3: MC2 (J14.18), MC3 (MC3.170)
PORTE_S4: MC2 (J14.19), MC3 (MC3.176)
PORTE_S5: MC2 (J14.20), MC3 (MC3.172)
PORTE_S6: MC2 (J14.21), MC3 (MC3.160)
PORTE_S7: MC2 (J14.22), MC3 (MC3.168)
PORTE_S8: MC2 (J14.23), MC3 (MC3.174)
PORTE_S9: MC2 (J14.24), MC3 (MC3.162)
QSFP_1_INT_B_3V3: MC1 (U3.19), QSFP-GTY (J8.28 R20.1)
QSFP_1_LP_MODE_3V3: MC1 (U3.15), QSFP-GTY (J8.31 R21.1)
QSFP_1_MODPRS_B_3V3: MC1 (U3.18), QSFP-GTY (J8.27 R19.1)
QSFP_1_MODSEL_B_3V3: MC1 (U3.16), QSFP-GTY (J8.8 R22.1)
QSFP_1_RESET_B_3V3: MC1 (U3.17), QSFP-GTY (J8.9 R23.1)
QSFP_1_RX1_N: MC1 (MC1.21), QSFP-GTY (J8.18)
QSFP_1_RX1_P: MC1 (MC1.19), QSFP-GTY (J8.17)
QSFP_1_RX2_N: MC1 (MC1.15), QSFP-GTY (J8.21)
QSFP_1_RX2_P: MC1 (MC1.13), QSFP-GTY (J8.22)
QSFP_1_RX3_N: MC1 (MC1.9), QSFP-GTY (J8.15)
QSFP_1_RX3_P: MC1 (MC1.7), QSFP-GTY (J8.14)
QSFP_1_RX4_N: MC1 (MC1.3), QSFP-GTY (J8.24)
QSFP_1_RX4_P: MC1 (MC1.1), QSFP-GTY (J8.25)
QSFP_1_SCL_3V3: MC1 (U3.13), QSFP-GTY (J8.11 R24.1)
QSFP_1_SDA_3V3: MC1 (U3.14), QSFP-GTY (J8.12 R28.1)
QSFP_1_TX1_N: MC1 (MC1.22), QSFP-GTY (J8.37)
QSFP_1_TX1_P: MC1 (MC1.20), QSFP-GTY (J8.36)
QSFP_1_TX2_N: MC1 (MC1.16), QSFP-GTY (J8.2)
QSFP_1_TX2_P: MC1 (MC1.14), QSFP-GTY (J8.3)
QSFP_1_TX3_N: MC1 (MC1.10), QSFP-GTY (J8.34)
QSFP_1_TX3_P: MC1 (MC1.8), QSFP-GTY (J8.33)
QSFP_1_TX4_N: MC1 (MC1.4), QSFP-GTY (J8.5)
QSFP_1_TX4_P: MC1 (MC1.2), QSFP-GTY (J8.6)
QSFP_2_INT_B_3V3: MC1 (U3.12), QSFP-GTY (J9.28 R86.1)
QSFP_2_LP_MODE_3V3: MC1 (U5.18), QSFP-GTY (J9.31 R87.1)
QSFP_2_MODPRS_B_3V3: MC1 (U3.11), QSFP-GTY (J9.27 R29.1)
QSFP_2_MODSEL_B_3V3: MC1 (U5.19), QSFP-GTY (J9.8 R88.1)
QSFP_2_RESET_B_3V3: MC1 (U3.10), QSFP-GTY (J9.9 R89.1)
QSFP_2_RX1_N: MC1 (MC1.51), QSFP-GTY (J9.18)
QSFP_2_RX1_P: MC1 (MC1.49), QSFP-GTY (J9.17)
QSFP_2_RX2_N: MC1 (MC1.45), QSFP-GTY (J9.21)
QSFP_2_RX2_P: MC1 (MC1.43), QSFP-GTY (J9.22)
QSFP_2_RX3_N: MC1 (MC1.39), QSFP-GTY (J9.15)
QSFP_2_RX3_P: MC1 (MC1.37), QSFP-GTY (J9.14)
QSFP_2_RX4_N: MC1 (MC1.33), QSFP-GTY (J9.24)
QSFP_2_RX4_P: MC1 (MC1.31), QSFP-GTY (J9.25)
QSFP_2_SCL_3V3: MC1 (U5.16), QSFP-GTY (J9.11 R90.1)
QSFP_2_SDA_3V3: MC1 (U5.17), QSFP-GTY (J9.12 R91.1)
QSFP_2_TX1_N: MC1 (MC1.52), QSFP-GTY (J9.37)
QSFP_2_TX1_P: MC1 (MC1.50), QSFP-GTY (J9.36)
QSFP_2_TX2_N: MC1 (MC1.46), QSFP-GTY (J9.2)
QSFP_2_TX2_P: MC1 (MC1.44), QSFP-GTY (J9.3)
QSFP_2_TX3_N: MC1 (MC1.40), QSFP-GTY (J9.34)
QSFP_2_TX3_P: MC1 (MC1.38), QSFP-GTY (J9.33)
QSFP_2_TX4_N: MC1 (MC1.34), QSFP-GTY (J9.5)
QSFP_2_TX4_P: MC1 (MC1.32), QSFP-GTY (J9.6)
QSFP_3_INT_B_3V3: MC1 (U5.15), QSFP-GTH (J30.28 R42.1)
QSFP_3_LP_MODE_3V3: MC1 (U5.11), QSFP-GTH (J30.31 R43.1)
QSFP_3_MODPRS_B_3V3: MC1 (U5.14), QSFP-GTH (J30.27 R46.1)
QSFP_3_MODSEL_B_3V3: MC1 (U5.12), QSFP-GTH (J30.8 R47.1)
QSFP_3_RESET_B_3V3: MC1 (U5.13), QSFP-GTH (J30.9 R80.1)
QSFP_3_RX1_N: MC2 (MC2.43), QSFP-GTH (J30.18)
QSFP_3_RX1_P: MC2 (MC2.41), QSFP-GTH (J30.17)
QSFP_3_RX2_N: MC2 (MC2.39), QSFP-GTH (J30.21)
QSFP_3_RX2_P: MC2 (MC2.37), QSFP-GTH (J30.22)
QSFP_3_RX3_N: MC2 (MC2.35), QSFP-GTH (J30.15)
QSFP_3_RX3_P: MC2 (MC2.33), QSFP-GTH (J30.14)
QSFP_3_RX4_N: MC2 (MC2.31), QSFP-GTH (J30.24)
QSFP_3_RX4_P: MC2 (MC2.29), QSFP-GTH (J30.25)
QSFP_3_SCL_3V3: MC1 (U8.18), QSFP-GTH (J30.11 R81.1)
QSFP_3_SDA_3V3: MC1 (U8.19), QSFP-GTH (J30.12 R82.1)
QSFP_3_TX1_N: MC2 (MC2.44), QSFP-GTH (J30.37)
QSFP_3_TX1_P: MC2 (MC2.42), QSFP-GTH (J30.36)
QSFP_3_TX2_N: MC2 (MC2.40), QSFP-GTH (J30.2)
QSFP_3_TX2_P: MC2 (MC2.38), QSFP-GTH (J30.3)
QSFP_3_TX3_N: MC2 (MC2.36), QSFP-GTH (J30.34)
QSFP_3_TX3_P: MC2 (MC2.34), QSFP-GTH (J30.33)
QSFP_3_TX4_N: MC2 (MC2.32), QSFP-GTH (J30.5)
QSFP_3_TX4_P: MC2 (MC2.30), QSFP-GTH (J30.6)
QSFP_4_INT_B_3V3: MC1 (U8.17), QSFP-GTH (J31.28 R45.1)
QSFP_4_LP_MODE_3V3: MC1 (U8.13), QSFP-GTH (J31.31 R52.1)
QSFP_4_MODPRS_B_3V3: MC1 (U8.16), QSFP-GTH (J31.27 R44.1)
QSFP_4_MODSEL_B_3V3: MC1 (U8.14), QSFP-GTH (J31.8 R53.1)
QSFP_4_RESET_B_3V3: MC1 (U8.15), QSFP-GTH (J31.9 R83.1)
QSFP_4_RX1_N: MC2 (MC2.63), QSFP-GTH (J31.18)
QSFP_4_RX1_P: MC2 (MC2.61), QSFP-GTH (J31.17)
QSFP_4_RX2_N: MC2 (MC2.59), QSFP-GTH (J31.21)
QSFP_4_RX2_P: MC2 (MC2.57), QSFP-GTH (J31.22)
QSFP_4_RX3_N: MC2 (MC2.55), QSFP-GTH (J31.15)
QSFP_4_RX3_P: MC2 (MC2.53), QSFP-GTH (J31.14)
QSFP_4_RX4_N: MC2 (MC2.51), QSFP-GTH (J31.24)
QSFP_4_RX4_P: MC2 (MC2.49), QSFP-GTH (J31.25)
QSFP_4_SCL_3V3: MC1 (U8.11), QSFP-GTH (J31.11 R84.1)
QSFP_4_SDA_3V3: MC1 (U8.12), QSFP-GTH (J31.12 R85.1)
QSFP_4_TX1_N: MC2 (MC2.64), QSFP-GTH (J31.37)
QSFP_4_TX1_P: MC2 (MC2.62), QSFP-GTH (J31.36)
QSFP_4_TX2_N: MC2 (MC2.60), QSFP-GTH (J31.2)
QSFP_4_TX2_P: MC2 (MC2.58), QSFP-GTH (J31.3)
QSFP_4_TX3_N: MC2 (MC2.56), QSFP-GTH (J31.34)
QSFP_4_TX3_P: MC2 (MC2.54), QSFP-GTH (J31.33)
QSFP_4_TX4_N: MC2 (MC2.52), QSFP-GTH (J31.5)
QSFP_4_TX4_P: MC2 (MC2.50), QSFP-GTH (J31.6)
SZG_SCL_3V3: MC1 (J3.1), MC2 (J14.1 R26.1 U19.6), MC3 (J4.1 J6.1 J7.1)
SZG_SDA_3V3: MC1 (J3.3), MC2 (J14.3 R25.1 U19.7), MC3 (J4.3 J6.3 J7.3)
XEM8370_PGOOD: Top (Q2.2 TP21.1), MC2 (MC2.15), Power (R76.2 S1.1)

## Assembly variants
Default: not fitted C51 C52 J5 J15 J16 J17 MC4 MC5 MC6 R3 R5 R9 R21 R22 R23 R43 R47 R52 R53 R69 R71 R75 R80 R83 R87 R88 R89 R97 R98 R99 S1 U6 U7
